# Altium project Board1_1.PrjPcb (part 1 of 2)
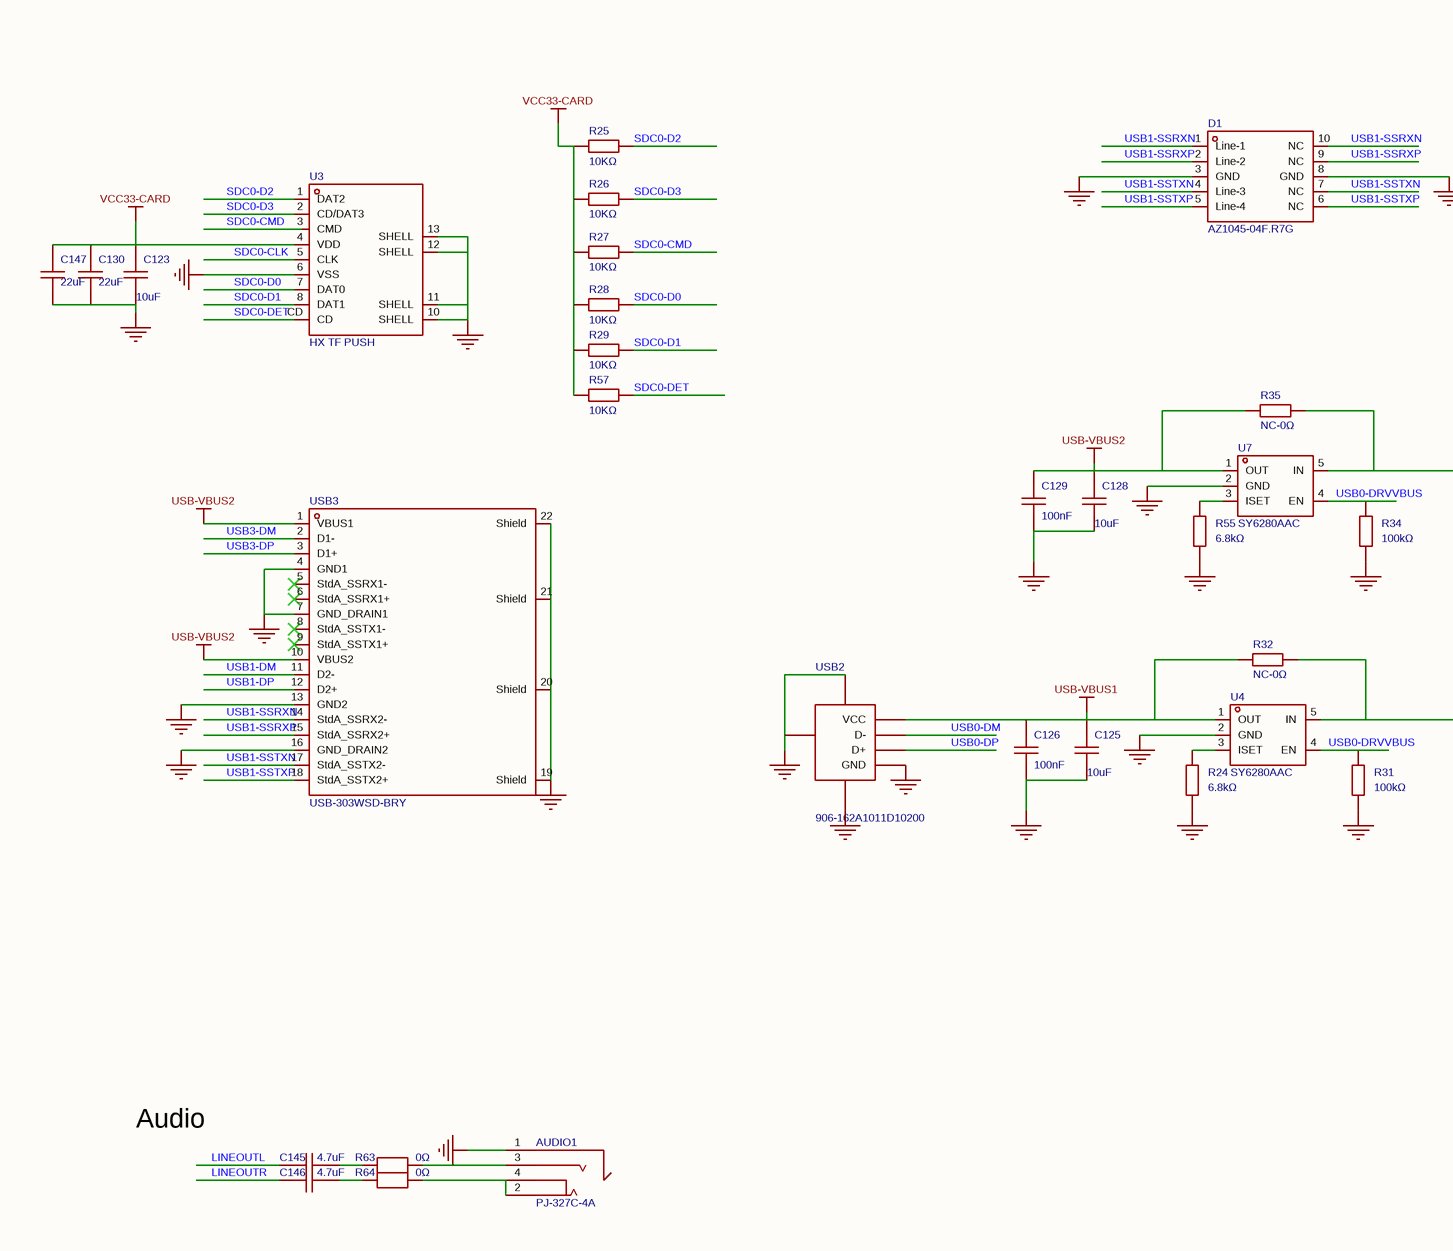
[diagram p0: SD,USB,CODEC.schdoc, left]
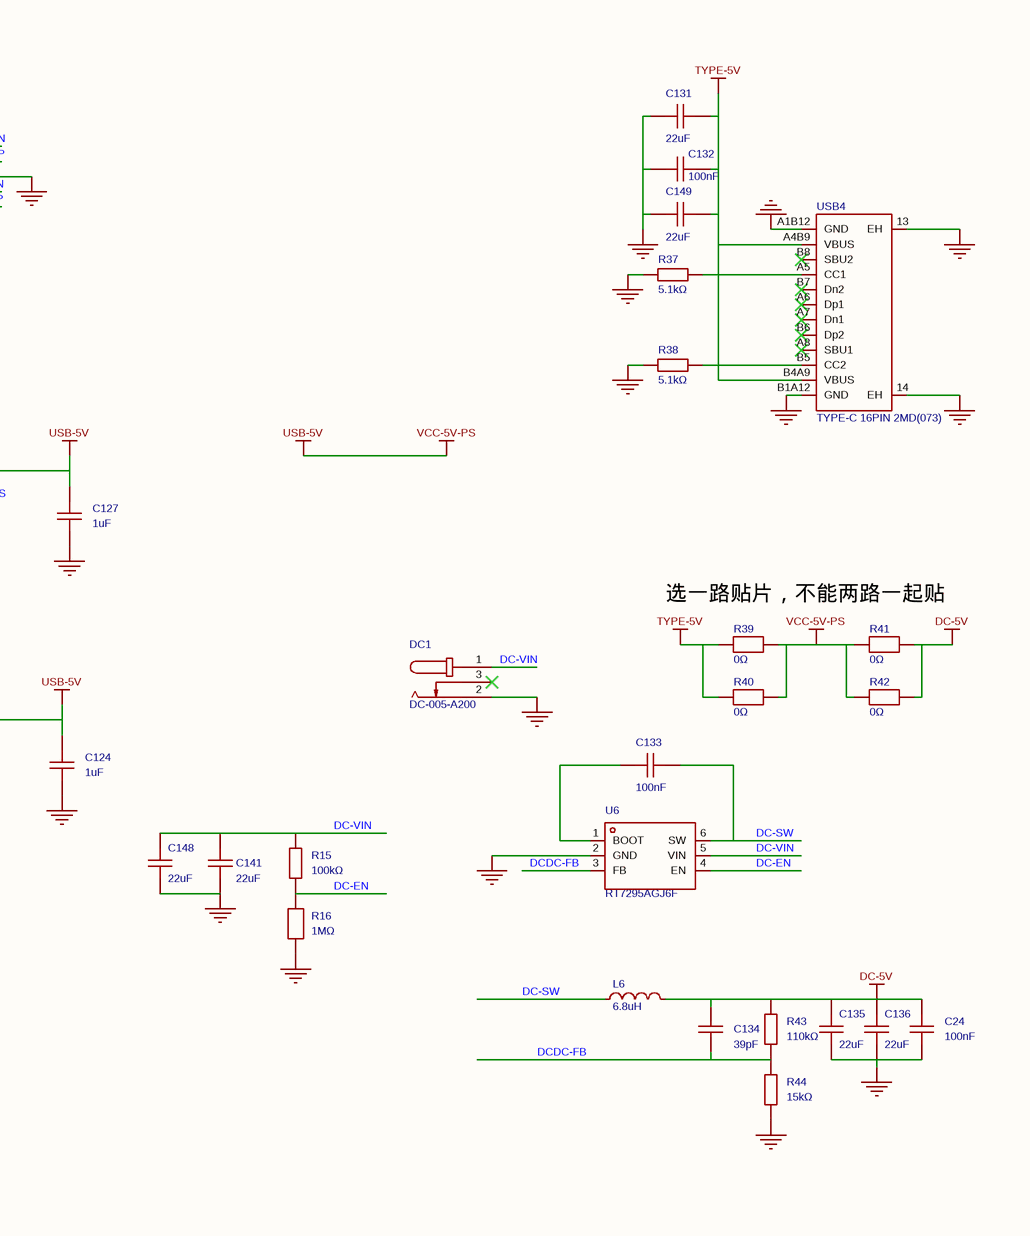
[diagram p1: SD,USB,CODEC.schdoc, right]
7 sheets, 256 parts. Net scope: global (net labels, ports and power ports of the same name join across sheets).
Board file: PCB1_1.pcbdoc
Sheets:
  SD,USB,CODEC.schdoc
  Lpddr3.schdoc
  H6_SOC_2.schdoc
  H6_SOC_1.schdoc
  Power_Tree_1.schdoc
  ETH,HDMI.schdoc
  KEY,DEBUG,LED.schdoc

## Sheet SD,USB,CODEC.schdoc
size 420 x 297 mm; Device: Drawing-Symbol_A4; @Board Name: Board1_1; @Page Name: SD,USB,CODEC; @Create Time: 13:52:28; @Page Count: 7; @Page No: 5; @Schematic Name: Schematic1_1; @Update Time: 13:52:28; @Assembly Variant: Basic; Border: 1; Title Block Position: 3; Size: A4; Region Start: 1; X Region Count: 6; Y Region Count: 4; Blade Width: 10; Width: 1655; Height: 1170; Symbol: Drawing-Symbol_A4; Company: 嘉立创EDA; Version: V1.0; Page Size: A4; @Project Name: N01｜全志 H6 Linux 主板; @Update Date: 2026-11-21; @Create Date: 2026-11-21

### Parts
AUDIO1  PJ-327C-4A  [AUDIO-SMD_PJ-327C-4A]
C24  100nF  [C0603]
C123  10uF  [C0603]
C124  1uF  [C0402]
C125  10uF  [C0603]
C126  100nF  [C0402]
C127  1uF  [C0402]
C128  10uF  [C0603]
C129  100nF  [C0402]
C130  22uF  [C0603]
C131  22uF  [C0603]
C132  100nF  [C0603]
C133  100nF  [C0603]
C134  39pF  [C0603]
C135  22uF  [C0603]
C136  22uF  [C0603]
C141  22uF  [C0603]
C145  4.7uF  [C0402]
C146  4.7uF  [C0402]
C147  22uF  [C0603]
C148  22uF  [C0603]
C149  22uF  [C0603]
D1  AZ1045-04F.R7G  [DFN2510-10_L2.5-W1.0-P0.50-BL]
DC1  DC-005-A200  [DC-IN-TH_DC-005-A200]
L6  6.8uH  [IND-SMD_L7.0-W6.6]
R15  100kΩ  [R0805]
R16  1MΩ  [R0805]
R24  6.8kΩ  [R0805]
R25  10KΩ  [R0805]
R26  10KΩ  [R0805]
R27  10KΩ  [R0805]
R28  10KΩ  [R0805]
R29  10KΩ  [R0805]
R31  100kΩ  [R0805]
R32  NC-0Ω  [R0805]
R34  100kΩ  [R0805]
R35  NC-0Ω  [R0805]
R37  5.1kΩ  [R0805]
R38  5.1kΩ  [R0805]
R39  0Ω  [R0805]
R40  0Ω  [R0805]
R41  0Ω  [R0805]
R42  0Ω  [R0805]
R43  110kΩ  [R0805]
R44  15kΩ  [R0805]
R55  6.8kΩ  [R0805]
R57  10KΩ  [R0805]
R63  0Ω  [R0805]
R64  0Ω  [R0805]
U3  HX TF PUSH  [TF-SMD_TF-PUSH]
U4  SY6280AAC  [SOT-23-5_L3.0-W1.7-P0.95-LS2.8-BL]
U6  RT7295AGJ6F  [SOT-23-6_L2.9-W1.6-P0.95-LS2.8-BR]
U7  SY6280AAC  [SOT-23-5_L3.0-W1.7-P0.95-LS2.8-BL]
USB2  906-162A1011D10200  [USB-A-TH_4P-P1.40-V-F-C39416]
USB3  USB-303WSD-BRY  [USB-A-TH_XUNPU_USB-303WSD-BRY]
USB4  TYPE-C 16PIN 2MD(073)  [USB-C-SMD_TYPE-C-16PIN-2MD-073]

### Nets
DC-5V: C24.2 C134.1 C135.2 C136.2 L6.2 R41.2 R42.2 R43.2
GND: AUDIO1.1 C24.1 C123.2 C124.1 C125.2 C126.1 C127.1 C128.2 C129.1 C130.1 C131.1 C132.2 C135.1 C136.1 C141.1 C147.1 C148.1 C149.2 D1.3(GND) D1.8(GND) DC1.2 R16.1 R24.1 R31.1 R34.1 R37.1 R38.1 R44.1 R55.1 U3.6(VSS) U3.10(SHELL) U3.11(SHELL) U3.12(SHELL) U3.13(SHELL) U4.2(GND) U6.2(GND) U7.2(GND) USB2.4(GND) USB2.5 USB2.6 USB2.7 USB3.4(GND1) USB3.7(GND_DRAIN1) USB3.13(GND2) USB3.16(GND_DRAIN2) USB3.19(Shield) USB3.20(Shield) USB3.21(Shield) USB3.22(Shield) USB4.13(EH) USB4.14(EH) USB4.A1B12(GND) USB4.B1A12(GND)
TYPE-5V: C131.2 C132.1 C149.1 R39.1 R40.1 USB4.A4B9(VBUS) USB4.B4A9(VBUS)
USB-5V: C124.2 C127.2 R32.1 R35.1 R39.2 R40.2 R41.1 R42.1 U4.5(IN) U7.5(IN)  [also labelled VCC-5V-PS]  [project net ALDOIN]
USB-VBUS1: C125.1 C126.2 R32.2 U4.1(OUT) USB2.1(VCC)
USB-VBUS2: C128.1 C129.2 R35.2 U7.1(OUT) USB3.1(VBUS1) USB3.10(VBUS2)
VCC33-CARD: C123.1 C130.2 C147.2 R25.2 R26.2 R27.2 R28.2 R29.2 R57.2 U3.4(VDD)  [project net CLDO1]
DC-EN: R15.1 R16.2 U6.4(EN)
DC-SW: C133.2 L6.1 U6.6(SW)
DC-VIN: C141.2 C148.2 DC1.1 R15.2 U6.5(VIN)
DCDC-FB: C134.2 R43.1 R44.2 U6.3(FB)
LINEOUTL: C145.2
LINEOUTR: C146.2
SDC0-CLK: U3.5(CLK)
SDC0-CMD: R27.1 U3.3(CMD)
SDC0-D0: R28.1 U3.7(DAT0)
SDC0-D1: R29.1 U3.8(DAT1)
SDC0-D2: R25.1 U3.1(DAT2)
SDC0-D3: R26.1 U3.2(CD/DAT3)
SDC0-DET: R57.1 U3.CD
USB0-DM: USB2.2(D-)
USB0-DP: USB2.3(D+)
USB0-DRVVBUS: R31.2 R34.2 U4.4(EN) U7.4(EN)
USB1-DM: USB3.11(D2-)
USB1-DP: USB3.12(D2+)
USB1-SSRXN: D1.1(Line-1) D1.10(NC) USB3.14(StdA_SSRX2-)
USB1-SSRXP: D1.2(Line-2) D1.9(NC) USB3.15(StdA_SSRX2+)
USB1-SSTXN: D1.4(Line-3) D1.7(NC) USB3.17(StdA_SSTX2-)
USB1-SSTXP: D1.5(Line-4) D1.6(NC) USB3.18(StdA_SSTX2+)
USB3-DM: USB3.2(D1-)
USB3-DP: USB3.3(D1+)
NetAUDIO1_2: AUDIO1.2 AUDIO1.4 R64.2
NetAUDIO1_3: AUDIO1.3 R63.2
NetC133_1: C133.1 U6.1(BOOT)
NetC145_1: C145.1 R63.1
NetC146_1: C146.1 R64.1
NetR24_2: R24.2 U4.3(ISET)
NetR37_2: R37.2 USB4.A5(CC1)
NetR38_2: R38.2 USB4.B5(CC2)
NetR55_2: R55.2 U7.3(ISET)

Not connected (* = marked no-connect by the designer): DC1 3*; USB3 5(StdA_SSRX1-)* 6(StdA_SSRX1+)* 8(StdA_SSTX1-)* 9(StdA_SSTX1+)*; USB4 A6(Dp1)* A7(Dn1)* A8(SBU1)* B6(Dp2)* B7(Dn2)* B8(SBU2)*

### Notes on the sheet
- (near R39) 选一路贴片，不能两路一起贴
- Audio

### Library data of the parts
AUDIO1 = PJ-327C-4A: 连接器类型:3.5mm耳机座;额定电流:500mA;额定电压:30V;触头材质:磷青铜;触头镀层:银;; Manufacturer: 韩国韩荣; AddInBom: yes; ModelId: b4a2275f591840bfadcc7ed8cf342a6c¦0819f05c4eef4c71ace90d822a990e87; ModelName: AUDIO-SMD_L11.8-W6.0-H5.0-4P; ModelTransform: 562.991,334.645,0,270,0,0,-7.124,73.506,-19.685; Current Rating: 500mA; Voltage Rating (Max): 30V
C24 C133 = FCC0603B104K500CT: 容值:100nF;精度:±10%;额定电压:50V;温度系数:X7R;; Manufacturer: FOJAN(富捷); 3D Model: ac125912035d415993ca9572d50418b1¦0819f05c4eef4c71ace90d822a990e87; 3D Model Transform: 62.992,31.496,0,0,0,0,0,0,0; Tolerance: ±10%; Voltage Rating: 50V; Temperature Coefficient: X7R; AddInBom: yes; ModelName: C0603_L1.6-W0.8-H0.8
C123 C125 C128 = CL10A106KP8NNNC: 容值:10uF;精度:±10%;额定电压:10V;温度系数:X5R;; Manufacturer: SAMSUNG(三星); 3D Model: ac125912035d415993ca9572d50418b1¦0819f05c4eef4c71ace90d822a990e87; 3D Model Transform: 62.992,31.496,0,0,0,0,0,0,0; Tolerance: ±10%; Voltage Rating: 10V; Temperature Coefficient: X5R; AddInBom: yes; ModelName: C0603_L1.6-W0.8-H0.8
C124 C127 = HGC0402R5105K500NTEJ: 容值:1uF;精度:±10%;额定电压:50V;温度系数:X5R;; Manufacturer: Chinocera(华瓷); 3D Model: 36a51122f27c49738f86b3bfa98863e0¦0819f05c4eef4c71ace90d822a990e87; 3D Model Transform: 39.37,19.685,0,0,0,0,0,0,0; Tolerance: ±10%; Voltage Rating: 50V; Temperature Coefficient: X5R; AddInBom: yes; ModelName: C0402_L1.0-W0.5-H0.5
C126 C129 = CL05B104KO5NNNC: 容值:100nF;精度:±10%;额定电压:16V;温度系数:X7R;; Manufacturer: SAMSUNG(三星); 3D Model: 36a51122f27c49738f86b3bfa98863e0¦0819f05c4eef4c71ace90d822a990e87; 3D Model Transform: 39.37,19.685,0,0,0,0,0,0,0; Tolerance: ±10%; Voltage Rating: 16V; Temperature Coefficient: X7R; AddInBom: yes; ModelName: C0402_L1.0-W0.5-H0.5
C130 C135 C136 C141 C147-C149 = HGC0603R5226M100NTHJ: 容值:22uF;精度:±20%;额定电压:10V;温度系数:X5R;; Manufacturer: Chinocera(华瓷); 3D Model: ac125912035d415993ca9572d50418b1¦0819f05c4eef4c71ace90d822a990e87; 3D Model Transform: 62.992,31.496,0,0,0,0,0,0,0; Tolerance: ±20%; Voltage Rating: 10V; Temperature Coefficient: X5R; AddInBom: yes; ModelName: C0603_L1.6-W0.8-H0.8
C131 = CGA0603X5R226M160JT: 容值:22uF;精度:±20%;额定电压:16V;温度系数:X5R;; Manufacturer: HRE(芯声); 3D Model: ac125912035d415993ca9572d50418b1¦0819f05c4eef4c71ace90d822a990e87; 3D Model Transform: 62.992,31.496,0,0,0,0,0,0,0; Tolerance: ±20%; Voltage Rating: 16V; Temperature Coefficient: X5R; AddInBom: yes; ModelName: C0603_L1.6-W0.8-H0.8
C132 = CGA0603X7R104K500JT: 容值:100nF;精度:±10%;额定电压:50V;温度系数:X7R;; Manufacturer: HRE(芯声); 3D Model: ac125912035d415993ca9572d50418b1¦0819f05c4eef4c71ace90d822a990e87; 3D Model Transform: 62.992,31.496,0,0,0,0,0,0,0; Tolerance: ±10%; Voltage Rating: 50V; Temperature Coefficient: X7R; AddInBom: yes; ModelName: C0603_L1.6-W0.8-H0.8
C134 = CC0603JRNPO9BN390: 容值:39pF;精度:±5%;额定电压:50V;温度系数:NP0;; Manufacturer: YAGEO(国巨); AddInBom: yes; ModelId: ac125912035d415993ca9572d50418b1¦0819f05c4eef4c71ace90d822a990e87; ModelName: C0603_L1.6-W0.8-H0.8; ModelTransform: 62.992,31.496,0,0,0,0,0,0,0; Tolerance: ±5%; Voltage Rating: 50V; Temperature Coefficient: NP0
C145 C146 = CL05A475KP5NRNC: 容值:4.7uF;精度:±10%;额定电压:10V;温度系数:X5R;; Manufacturer: SAMSUNG(三星); AddInBom: yes; ModelId: 36a51122f27c49738f86b3bfa98863e0¦0819f05c4eef4c71ace90d822a990e87; ModelName: C0402_L1.0-W0.5-H0.5; ModelTransform: 39.37,19.685,0,0,0,0,0,0,0; Tolerance: ±10%; Voltage Rating: 10V; Temperature Coefficient: X5R
D1 = AZ1045-04F.R7G: 反向截止电压(Vrwm):5V;钳位电压:12V;峰值脉冲电流(Ipp):3.5A@8/20us;峰值脉冲功率(Ppp):30W@8/20us;击穿电压:6V;; Manufacturer: AMAZING(晶焱); AddInBom: yes; ModelId: 55525fa8fc914f7c8ffcb10749ea5f73¦0819f05c4eef4c71ace90d822a990e87; ModelName: DFN-10_L2.5-W1.0-H0.5-P0.50; ModelTransform: 40.1574,98.425,0,90,0,0,0,0,0; Reverse Stand-Off Voltage (Vrwm): 5V; Clamping Voltage: 12V; Voltage - Breakdown: 6V; Reverse Leakage Current (Ir): 1.5uA; Number of Channels: 四路; level of protection: IEC 61000-4-5；IEC 61000-4-2; Type: ESD; Junction Capacitance: 0.5pF
DC1 = DC-005-A200: 连接器类型:DC电源插座;安装方式:弯插;触点内径:2mm;触点外径:6.4mm;额定电流:3A;额定电压:30V;工作温度:-20℃~+70℃;; Manufacturer: XUNPU(讯普); AddInBom: yes; ModelId: 1321cdbe1dc84555a9684967491c8670¦0819f05c4eef4c71ace90d822a990e87; ModelTransform: 553.149,368.14887,0,0,0,0,-137.795,85.63,-161.417; Connector Type: DC电源插座; Inside Contact Diameter: 2mm; Outside Contact Diameter: 6.4mm; Current Rating: 3A; Voltage Rating (Max): 30V
L6 = FXL0630-6R8-M: 电感值:6.8uH;精度:±20%;额定电流:5A;饱和电流(Isat):6A;类型:一体成型电感;; Manufacturer: cjiang(长江微电); AddInBom: yes; ModelId: 6860c29aec394a38a0f014af7f722a42¦0819f05c4eef4c71ace90d822a990e87; ModelName: IND-SMD_L7.0-W6.6-H3.0; ModelTransform: 275.59,259.88137,0,0,0,0,0,0,0; Tolerance: ±20%; Current Rating: 5A; Current - Saturation(Isat): 6A; DC Resistance(DCR): 48mΩ; Type: 一体成型电感
R15 = 0805W8F1003T5E: 电阻类型:厚膜电阻;阻值:100kΩ;精度:±1%;功率:125mW;工作电压:150V;温度系数:±100ppm/℃;; Manufacturer: UNI-ROYAL(厚声); Symbol: 0805W8F1003T5E_C149504; 3D Model: 37a81e68749a4138bd2dfa6897b24b85¦0819f05c4eef4c71ace90d822a990e87; 3D Model Transform: 78.74,51.181,0,0,0,0,0,-0.0005,0; Tolerance: ±1%; Power(Watts): 125mW; Voltage-Supply(Max): 150V; AddInBom: yes; ModelName: R0805_L2.0-W1.3-H0.6
R16 = AS051MF: 阻值:1MΩ;精度:±1%;功率:125mW;工作电压:150V;温度系数:±100ppm/℃;; Manufacturer: HKR(香港电阻); AddInBom: yes; ModelId: 37a81e68749a4138bd2dfa6897b24b85¦0819f05c4eef4c71ace90d822a990e87; ModelName: R0805_L2.0-W1.3-H0.6; ModelTransform: 78.74,51.181,0,0,0,0,0,-0.0005,0; Tolerance: ±1%; Power(Watts): 125mW; Voltage-Supply(Max): 150V
R24 R55 = 0805W8F6801T5E: 电阻类型:厚膜电阻;阻值:6.8kΩ;精度:±1%;功率:125mW;工作电压:150V;温度系数:±100ppm/℃;; Manufacturer: UNI-ROYAL(厚声); AddInBom: yes; ModelId: 37a81e68749a4138bd2dfa6897b24b85¦0819f05c4eef4c71ace90d822a990e87; ModelName: R0805_L2.0-W1.3-H0.6; ModelTransform: 78.74,51.181,0,0,0,0,0,-0.0005,0; Tolerance: ±1%; Power(Watts): 125mW; Voltage-Supply(Max): 150V
R25-R29 R57 = 0805W8F1002T5E_C17414: 电阻类型:厚膜电阻;阻值:10kΩ;精度:±1%;功率:125mW;工作电压:150V;温度系数:±100ppm/℃;; Manufacturer: UNI-ROYAL(厚声); Add into BOM: yes; 3D Model: 37a81e68749a4138bd2dfa6897b24b85; 3D Model Transform: 78.74,51.181,0,0,0,0,0,-0.0005,0; Tolerance: ±1%; Power(Watts): 125mW; Voltage-Supply(Max): 150V; ModelName: R0805_L2.0-W1.3-H0.6
R31 R32 R34 R35 = 0805W8F1003T5E: 电阻类型:厚膜电阻;阻值:100kΩ;精度:±1%;功率:125mW;工作电压:150V;温度系数:±100ppm/℃;; Manufacturer: UNI-ROYAL(厚声); Symbol: 0805W8F1003T5E_C149504; AddInBom: yes; ModelId: 37a81e68749a4138bd2dfa6897b24b85¦0819f05c4eef4c71ace90d822a990e87; ModelName: R0805_L2.0-W1.3-H0.6; ModelTransform: 78.74,51.181,0,0,0,0,0,-0.0005,0; Tolerance: ±1%; Power(Watts): 125mW; Voltage-Supply(Max): 150V
R37 R38 = 0805W8F5101T5E: 电阻类型:厚膜电阻;阻值:5.1kΩ;精度:±1%;功率:125mW;工作电压:150V;温度系数:±100ppm/℃;; Manufacturer: UNI-ROYAL(厚声); 3D Model: 37a81e68749a4138bd2dfa6897b24b85¦0819f05c4eef4c71ace90d822a990e87; 3D Model Transform: 78.74,51.181,0,0,0,0,0,-0.0005,0; Tolerance: ±1%; Power(Watts): 125mW; Voltage-Supply(Max): 150V; AddInBom: yes; ModelName: R0805_L2.0-W1.3-H0.6
R39-R42 R63 R64 = RE0805FAR000: 电阻类型:合金电阻;阻值:0Ω;精度:±1%;功率:500mW;温度系数:±50ppm/℃;安装方式:贴片;; Manufacturer: JIERR(捷而瑞); 3D Model: 37a81e68749a4138bd2dfa6897b24b85¦0819f05c4eef4c71ace90d822a990e87; 3D Model Transform: 78.74,51.181,0,0,0,0,0,-0.0005,0; Tolerance: ±1%; Power(Watts): 500mW; AddInBom: yes; ModelName: R0805_L2.0-W1.3-H0.6
R43 = 0805W8F1103T5E: 电阻类型:厚膜电阻;阻值:110kΩ;精度:±1%;功率:125mW;工作电压:150V;温度系数:±100ppm/℃;; Manufacturer: UNI-ROYAL(厚声); AddInBom: yes; ModelId: 37a81e68749a4138bd2dfa6897b24b85¦0819f05c4eef4c71ace90d822a990e87; ModelName: R0805_L2.0-W1.3-H0.6; ModelTransform: 78.74,51.181,0,0,0,0,0,-0.0005,0; Tolerance: ±1%; Power(Watts): 125mW; Voltage-Supply(Max): 150V
R44 = 0805W8F1502T5E: 电阻类型:厚膜电阻;阻值:15kΩ;精度:±1%;功率:125mW;工作电压:150V;温度系数:±100ppm/℃;; Manufacturer: UNI-ROYAL(厚声); AddInBom: yes; ModelId: 37a81e68749a4138bd2dfa6897b24b85¦0819f05c4eef4c71ace90d822a990e87; ModelName: R0805_L2.0-W1.3-H0.6; ModelTransform: 78.74,51.181,0,0,0,0,0,-0.0005,0; Tolerance: ±1%; Power(Watts): 125mW; Voltage-Supply(Max): 150V
U3 = HX TF PUSH: 卡连接方式:自弹式;卡类型:MicroSD卡(TF卡);连接器类型:卡座;本体最大高度:2mm;工作温度:-20℃~+70℃;; Manufacturer: hanxia(韩下); 3D Model: 2d6270e77c9a43c6bb0aca962ba811a2¦0819f05c4eef4c71ace90d822a990e87; 3D Model Transform: 635.826,598.424,0,0,0,0,0.002,-82.441,-23.622; Card Connection Mode: 自弹式; Connector Type: 卡座; Additional Card Detection Pins: 有; Rated Voltage (Max): 5V; AddInBom: yes
U4 U7 = SY6280AAC_C55136: 类型:高侧开关;通道数:1;输入控制逻辑:高电平有效;工作电压:2.4V~5.5V;最大连续电流:2A;导通电阻:80mΩ;; Manufacturer: Silergy(矽力杰); AddInBom: yes; ModelId: 0a2a1b8f50944f73965918ad6e5fe167¦0819f05c4eef4c71ace90d822a990e87; ModelName: SOT-23-5_L2.9-W1.6-H1.1-LS2.8-P0.95; ModelTransform: 118.60433,114.173,0,90,0,0,0.0005,0.0005,0; Number of Channels: 1; Control Input Logic: 高电平有效; Maximum Continuous Current: 2A; RDS(on): 80mΩ
U6 = RT7295AGJ6F: 功能类型:降压型;工作电压:4.3V~18V;输出电压:600mV~8V;输出电流:3.5A;输出类型:可调;; Manufacturer: RICHTEK(立锜); AddInBom: yes; ModelId: 18da8f6c14a34920b3e136b5c401a119¦0819f05c4eef4c71ace90d822a990e87; ModelName: SOT-23-6_L2.9-W1.6-H1.5-LS2.8-P0.95; ModelTransform: 110.73671,114.173,0,180,0,0,0.001,-0.003,0; Function: 降压型; Output Current: 3.5A; Frequency - Switching: 500kHz; Synchronous Rectifier: 是; Number of Outputs: 1; Topology: 降压式; Quiescent Current: 500uA; Switch tube (built-in/external): 内置; Output Type: 可调
USB2 = 906-162A1011D10200: 连接器类型:Type-A;协议标准:USB 2.0;公母:母;安装方式:侧插;触点数量:4P;端口数量:1;额定电流 - 电源:2A;工作温度:-;; Manufacturer: 精拓金; Symbol: AFSide of the three straight feet boundless copper14.0PBTWhite plastic90degree; AddInBom: yes; ModelId: bcfe7919af774627a59aba49c9f8feb0¦0819f05c4eef4c71ace90d822a990e87; ModelTransform: 280.3144,555.121,0,0,0,0,0,-74.212,-118.11; Connector Type: Type-A; Protocol Standard: USB 2.0; Gender: 母; Number of Contacts: 4P; Number of Ports: 1; Current Rating-Power: 2A; Voltage Rating: 30V; Connect-Disconnect Life: 1.5千次
USB3 = USB-303WSD-BRY: 连接器类型:Type-A;协议标准:USB 3.0;公母:母;安装方式:弯插;触点数量:9Px2;端口数量:2;额定电流 - 电源:1.8A;工作温度:-30℃~+85℃;; Manufacturer: XUNPU(讯普); AddInBom: yes; ModelId: 099f7116bbdc404e98854c37ac96170a¦0819f05c4eef4c71ace90d822a990e87; ModelTransform: 614.147,688.975,0,0,0,0,0,-166.339,-118.11; Connector Type: Type-A; Protocol Standard: USB 3.0; Gender: 母; Number of Contacts: 9Px2; Number of Ports: 2; Current Rating-Power: 1.8A; Voltage Rating: 30V; Detection color: 蓝色
USB4 = TYPE-C 16PIN 2MD(073): 连接器类型:Type-C;协议标准:-;公母:母;安装方式:卧贴;触点数量:16P;端口数量:1;额定电流 - 电源:3A;工作温度:-25℃~+85℃;; Manufacturer: SHOU HAN(首韩); Add into BOM: yes; 3D Model: 3a41b9ec9b654a0fad4d118405ec6290; 3D Model Transform: 351.9678,298.4246,0,0,0,0,0,-47.244,-35.433; Gender: 母; Number of Contacts: 16P; Number of Ports: 1; Current Rating-Power: 3A; Voltage Rating: 5V; Connect-Disconnect Life: 1万次; Detection color: 黑色; ModelName: USB-C-SMD_TYPE-C-6PIN-2MD-073

## Sheet Lpddr3.schdoc
size 420 x 297 mm; Device: Drawing-Symbol_A4; @Board Name: Board1_1; @Page Name: Lpddr3; @Create Time: 13:52:28; @Page Count: 7; @Page No: 4; @Schematic Name: Schematic1_1; @Update Time: 13:52:28; @Assembly Variant: Basic; Border: 1; Title Block Position: 3; Size: A4; Region Start: 1; X Region Count: 6; Y Region Count: 4; Blade Width: 10; Width: 1655; Height: 1170; Symbol: Drawing-Symbol_A4; Company: 嘉立创EDA; Version: V1.0; Page Size: A4; @Project Name: N01｜全志 H6 Linux 主板; @Update Date: 2026-11-21; @Create Date: 2026-11-21
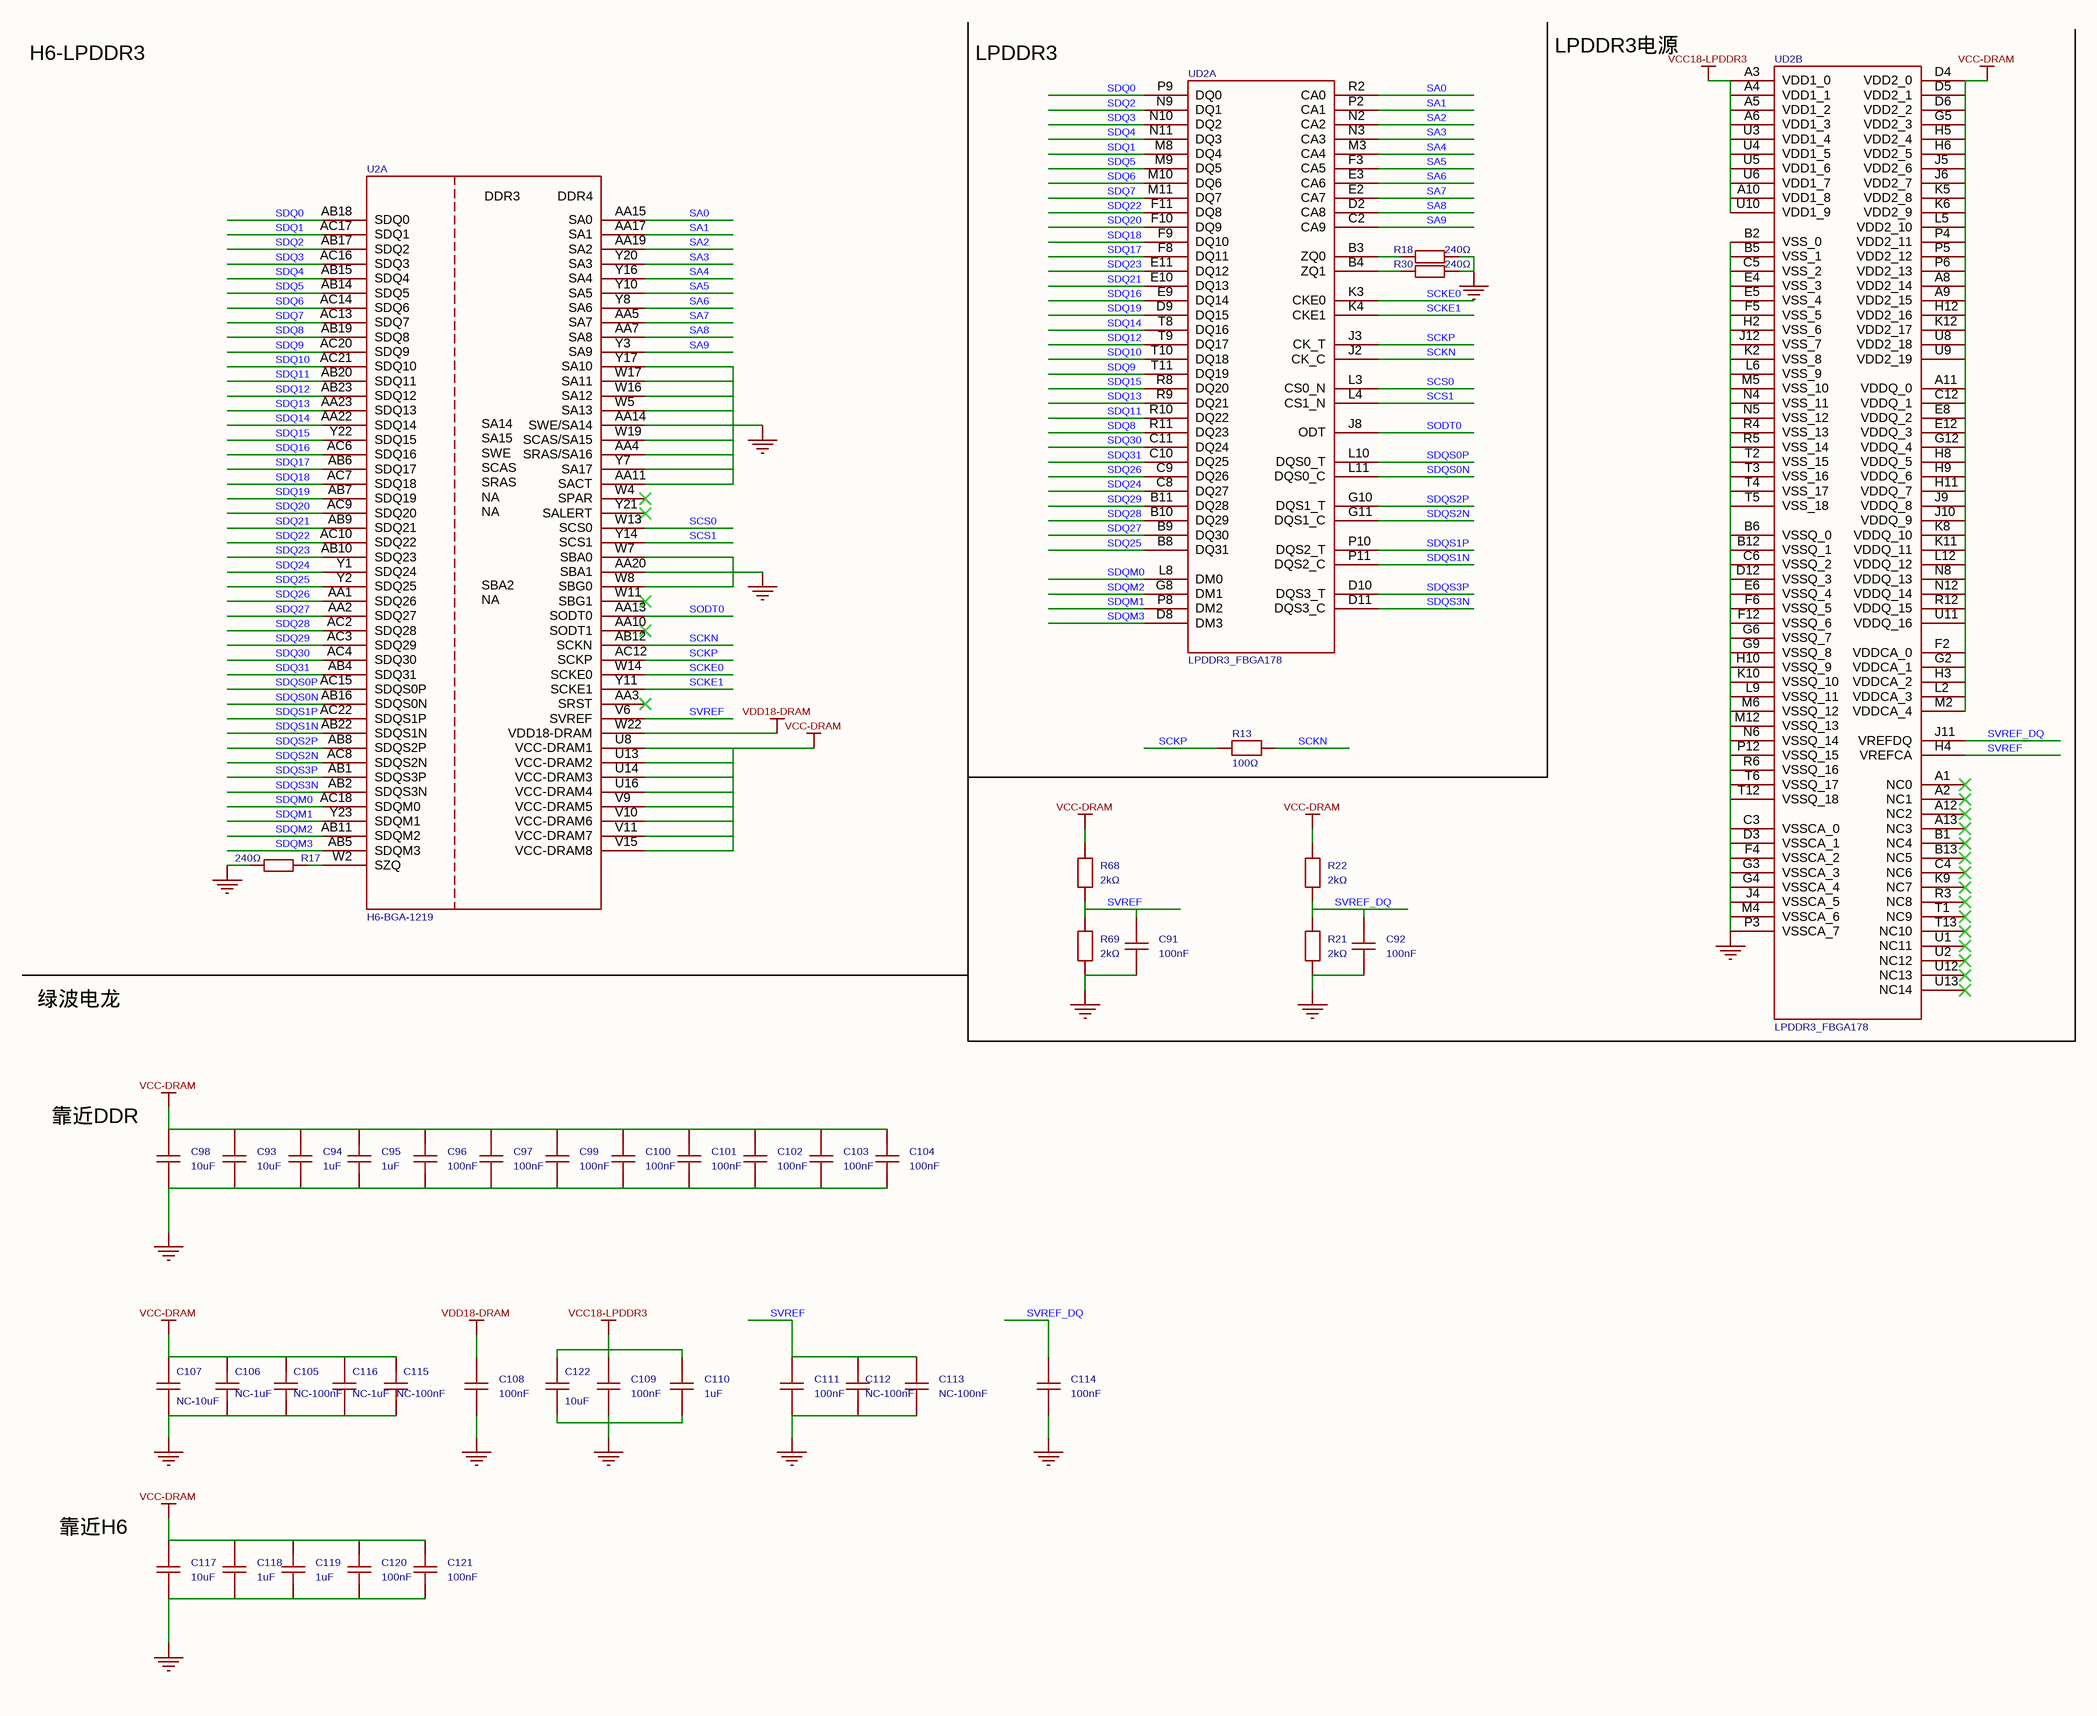
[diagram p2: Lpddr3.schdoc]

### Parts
C91  100nF  [C0402]
C92  100nF  [C0402]
C93  10uF  [C0603]
C94  1uF  [C0402]
C95  1uF  [C0402]
C96  100nF  [C0402]
C97  100nF  [C0402]
C98  10uF  [C0603]
C99  100nF  [C0402]
C100  100nF  [C0402]
C101  100nF  [C0402]
C102  100nF  [C0402]
C103  100nF  [C0402]
C104  100nF  [C0402]
C105  NC-100nF  [C0402]
C106  NC-1uF  [C0402]
C107  NC-10uF  [C0603]
C108  100nF  [C0402]
C109  100nF  [C0402]
C110  1uF  [C0402]
C111  100nF  [C0402]
C112  NC-100nF  [C0402]
C113  NC-100nF  [C0402]
C114  100nF  [C0402]
C115  NC-100nF  [C0402]
C116  NC-1uF  [C0402]
C117  10uF  [C0603]
C118  1uF  [C0402]
C119  1uF  [C0402]
C120  100nF  [C0402]
C121  100nF  [C0402]
C122  10uF  [C0603]
R13  100Ω  [R0805]
R17  240Ω  [R0805]
R18  240Ω  [R0805]
R21  2kΩ  [R0402]
R22  2kΩ  [R0402]
R30  240Ω  [R0805]
R68  2kΩ  [R0402]
R69  2kΩ  [R0402]
U2  H6-BGA-1219  [H6_BGA451]  (part A of 4)
UD2  LPDDR3_FBGA178  [LPDDR3_FBGA178]  (parts A,B of 2)

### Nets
GND: C91.1 C92.1 C93.1 C94.1 C95.1 C96.1 C97.1 C98.1 C99.1 C100.1 C101.1 C102.1 C103.1 C104.1 C105.1 C106.1 C107.1 C108.1 C109.1 C110.1 C111.1 C112.1 C113.1 C114.1 C115.1 C116.1 C117.1 C118.1 C119.1 C120.1 C121.1 C122.1 R17.1 R18.2 R21.1 R30.2 R69.1 U2.AA4(SRAS/SA16) U2.AA11(SACT) U2.AA14(SWE/SA14) U2.AA20(SBA1) U2.W5(SA13) U2.W7(SBA0) U2.W8(SBG0) U2.W16(SA12) U2.W17(SA11) U2.W19(SCAS/SA15) U2.Y7(SA17) U2.Y17(SA10) UD2.B2(VSS_0) UD2.B5(VSS_1) UD2.B6(VSSQ_0) UD2.B12(VSSQ_1) UD2.C3(VSSCA_0) UD2.C5(VSS_2) UD2.C6(VSSQ_2) UD2.D3(VSSCA_1) UD2.D12(VSSQ_3) UD2.E4(VSS_3) UD2.E5(VSS_4) UD2.E6(VSSQ_4) UD2.F4(VSSCA_2) UD2.F5(VSS_5) UD2.F6(VSSQ_5) UD2.F12(VSSQ_6) UD2.G3(VSSCA_3) UD2.G4(VSSCA_4) UD2.G6(VSSQ_7) UD2.G9(VSSQ_8) UD2.H2(VSS_6) UD2.H10(VSSQ_9) UD2.J4(VSSCA_5) UD2.J12(VSS_7) UD2.K2(VSS_8) UD2.K10(VSSQ_10) UD2.L6(VSS_9) UD2.L9(VSSQ_11) UD2.M4(VSSCA_6) UD2.M5(VSS_10) UD2.M6(VSSQ_12) UD2.M12(VSSQ_13) UD2.N4(VSS_11) UD2.N5(VSS_12) UD2.N6(VSSQ_14) UD2.P3(VSSCA_7) UD2.P12(VSSQ_15) UD2.R4(VSS_13) UD2.R5(VSS_14) UD2.R6(VSSQ_16) UD2.T2(VSS_15) UD2.T3(VSS_16) UD2.T4(VSS_17) UD2.T5(VSS_18) UD2.T6(VSSQ_17) UD2.T12(VSSQ_18)
VCC18-LPDDR3: C109.2 C110.2 C122.2 UD2.A3(VDD1_0) UD2.A4(VDD1_1) UD2.A5(VDD1_2) UD2.A6(VDD1_3) UD2.A10(VDD1_8) UD2.U3(VDD1_4) UD2.U4(VDD1_5) UD2.U5(VDD1_6) UD2.U6(VDD1_7) UD2.U10(VDD1_9)
VCC-DRAM: C93.2 C94.2 C95.2 C96.2 C97.2 C98.2 C99.2 C100.2 C101.2 C102.2 C103.2 C104.2 C105.2 C106.2 C107.2 C115.2 C116.2 C117.2 C118.2 C119.2 C120.2 C121.2 R22.2 R68.2 U2.U8(VCC-DRAM1) U2.U13(VCC-DRAM2) U2.U14(VCC-DRAM3) U2.U16(VCC-DRAM4) U2.V9(VCC-DRAM5) U2.V10(VCC-DRAM6) U2.V11(VCC-DRAM7) U2.V15(VCC-DRAM8) UD2.A8(VDD2_14) UD2.A9(VDD2_15) UD2.A11(VDDQ_0) UD2.C12(VDDQ_1) UD2.D4(VDD2_0) UD2.D5(VDD2_1) UD2.D6(VDD2_2) UD2.E8(VDDQ_2) UD2.E12(VDDQ_3) UD2.F2(VDDCA_0) UD2.G2(VDDCA_1) UD2.G5(VDD2_3) UD2.G12(VDDQ_4) UD2.H3(VDDCA_2) UD2.H5(VDD2_4) UD2.H6(VDD2_5) UD2.H8(VDDQ_5) UD2.H9(VDDQ_6) UD2.H11(VDDQ_7) UD2.H12(VDD2_16) UD2.J5(VDD2_6) UD2.J6(VDD2_7) UD2.J9(VDDQ_8) UD2.J10(VDDQ_9) UD2.K5(VDD2_8) UD2.K6(VDD2_9) UD2.K8(VDDQ_10) UD2.K11(VDDQ_11) UD2.K12(VDD2_17) UD2.L2(VDDCA_3) UD2.L5(VDD2_10) UD2.L12(VDDQ_12) UD2.M2(VDDCA_4) UD2.N8(VDDQ_13) UD2.N12(VDDQ_14) UD2.P4(VDD2_11) UD2.P5(VDD2_12) UD2.P6(VDD2_13) UD2.R12(VDDQ_15) UD2.U8(VDD2_18) UD2.U9(VDD2_19) UD2.U11(VDDQ_16)  [project net DCDCE]
VDD18-DRAM: C108.2 U2.W22(VDD18-DRAM)  [project net BLDO1]
SA0: U2.AA15(SA0) UD2.R2(CA0)
SA1: U2.AA17(SA1) UD2.P2(CA1)
SA2: U2.AA19(SA2) UD2.N2(CA2)
SA3: U2.Y20(SA3) UD2.N3(CA3)
SA4: U2.Y16(SA4) UD2.M3(CA4)
SA5: U2.Y10(SA5) UD2.F3(CA5)
SA6: U2.Y8(SA6) UD2.E3(CA6)
SA7: U2.AA5(SA7) UD2.E2(CA7)
SA8: U2.AA7(SA8) UD2.D2(CA8)
SA9: U2.Y3(SA9) UD2.C2(CA9)
SCKE0: U2.W14(SCKE0) UD2.K3(CKE0)
SCKE1: U2.Y11(SCKE1) UD2.K4(CKE1)
SCKN: R13.2 U2.AB12(SCKN) UD2.J2(CK_C)
SCKP: R13.1 U2.AC12(SCKP) UD2.J3(CK_T)
SCS0: U2.W13(SCS0) UD2.L3(CS0_N)
SCS1: U2.Y14(SCS1) UD2.L4(CS1_N)
SDQ0: U2.AB18(SDQ0) UD2.P9(DQ0)
SDQ1: U2.AC17(SDQ1) UD2.M8(DQ4)
SDQ2: U2.AB17(SDQ2) UD2.N9(DQ1)
SDQ3: U2.AC16(SDQ3) UD2.N10(DQ2)
SDQ4: U2.AB15(SDQ4) UD2.N11(DQ3)
SDQ5: U2.AB14(SDQ5) UD2.M9(DQ5)
SDQ6: U2.AC14(SDQ6) UD2.M10(DQ6)
SDQ7: U2.AC13(SDQ7) UD2.M11(DQ7)
SDQ8: U2.AB19(SDQ8) UD2.R11(DQ23)
SDQ9: U2.AC20(SDQ9) UD2.T11(DQ19)
SDQ10: U2.AC21(SDQ10) UD2.T10(DQ18)
SDQ11: U2.AB20(SDQ11) UD2.R10(DQ22)
SDQ12: U2.AB23(SDQ12) UD2.T9(DQ17)
SDQ13: U2.AA23(SDQ13) UD2.R9(DQ21)
SDQ14: U2.AA22(SDQ14) UD2.T8(DQ16)
SDQ15: U2.Y22(SDQ15) UD2.R8(DQ20)
SDQ16: U2.AC6(SDQ16) UD2.E9(DQ14)
SDQ17: U2.AB6(SDQ17) UD2.F8(DQ11)
SDQ18: U2.AC7(SDQ18) UD2.F9(DQ10)
SDQ19: U2.AB7(SDQ19) UD2.D9(DQ15)
SDQ20: U2.AC9(SDQ20) UD2.F10(DQ9)
SDQ21: U2.AB9(SDQ21) UD2.E10(DQ13)
SDQ22: U2.AC10(SDQ22) UD2.F11(DQ8)
SDQ23: U2.AB10(SDQ23) UD2.E11(DQ12)
SDQ24: U2.Y1(SDQ24) UD2.C8(DQ27)
SDQ25: U2.Y2(SDQ25) UD2.B8(DQ31)
SDQ26: U2.AA1(SDQ26) UD2.C9(DQ26)
SDQ27: U2.AA2(SDQ27) UD2.B9(DQ30)
SDQ28: U2.AC2(SDQ28) UD2.B10(DQ29)
SDQ29: U2.AC3(SDQ29) UD2.B11(DQ28)
SDQ30: U2.AC4(SDQ30) UD2.C11(DQ24)
SDQ31: U2.AB4(SDQ31) UD2.C10(DQ25)
SDQM0: U2.AC18(SDQM0) UD2.L8(DM0)
SDQM1: U2.Y23(SDQM1) UD2.P8(DM2)
SDQM2: U2.AB11(SDQM2) UD2.G8(DM1)
SDQM3: U2.AB5(SDQM3) UD2.D8(DM3)
SDQS0N: U2.AB16(SDQS0N) UD2.L11(DQS0_C)
SDQS0P: U2.AC15(SDQS0P) UD2.L10(DQS0_T)
SDQS1N: U2.AB22(SDQS1N) UD2.P11(DQS2_C)
SDQS1P: U2.AC22(SDQS1P) UD2.P10(DQS2_T)
SDQS2N: U2.AC8(SDQS2N) UD2.G11(DQS1_C)
SDQS2P: U2.AB8(SDQS2P) UD2.G10(DQS1_T)
SDQS3N: U2.AB2(SDQS3N) UD2.D11(DQS3_C)
SDQS3P: U2.AB1(SDQS3P) UD2.D10(DQS3_T)
SODT0: U2.AA13(SODT0) UD2.J8(ODT)
SVREF: C91.2 C111.2 C112.2 C113.2 R68.1 R69.2 U2.V6(SVREF) UD2.H4(VREFCA)
SVREF_DQ: C92.2 C114.2 R21.2 R22.1 UD2.J11(VREFDQ)
NetR17_2: R17.2 U2.W2(SZQ)
NetR18_1: R18.1 UD2.B3(ZQ0)
NetR30_1: R30.1 UD2.B4(ZQ1)

Not connected (* = marked no-connect by the designer): U2 AA3(SRST)* AA10(SODT1)* W4(SPAR)* W11(SBG1)* Y21(SALERT)*; UD2 A1(NC0)* A2(NC1)* A12(NC2)* A13(NC3)* B1(NC4)* B13(NC5)* C4(NC6)* K9(NC7)* R3(NC8)* T1(NC9)* T13(NC10)* U1(NC11)* U2(NC12)* U12(NC13)* U13(NC14)*

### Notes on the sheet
- H6-LPDDR3
- LPDDR3
- LPDDR3电源
- 绿波电龙
- 靠近DDR
- 靠近H6

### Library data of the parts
C91 C92 C96 C97 C99-C105 C108 C109 C111-C115 C120 C121 = CL05B104KO5NNNC: as C126 on sheet SD,USB,CODEC
C93 C98 C107 C117 C122 = FCC0603X106K100CT: 容值:10uF;精度:±10%;额定电压:10V;温度系数:X5R;; Manufacturer: FOJAN(富捷); 3D Model: ac125912035d415993ca9572d50418b1¦0819f05c4eef4c71ace90d822a990e87; 3D Model Transform: 62.992,31.496,0,0,0,0,0,0,0; Tolerance: ±10%; Voltage Rating: 10V; Temperature Coefficient: X5R; AddInBom: yes; ModelName: C0603_L1.6-W0.8-H0.8
C94 C95 C106 C110 C116 C118 C119 = HGC0402R5105K500NTEJ: as C124 on sheet SD,USB,CODEC
R13 = FRC0805F1000TS: 电阻类型:厚膜电阻;阻值:100Ω;精度:±1%;功率:125mW;工作电压:150V;温度系数:±100ppm/℃;; Manufacturer: FOJAN(富捷); AddInBom: yes; ModelId: 37a81e68749a4138bd2dfa6897b24b85¦0819f05c4eef4c71ace90d822a990e87; ModelName: R0805_L2.0-W1.3-H0.6; ModelTransform: 78.74,51.181,0,0,0,0,0,-0.0005,0; Tolerance: ±1%; Power(Watts): 125mW; Voltage-Supply(Max): 150V
R17 R18 = 0805W8F2400T5E: 电阻类型:厚膜电阻;阻值:240Ω;精度:±1%;功率:125mW;工作电压:150V;温度系数:±100ppm/℃;; Manufacturer: UNI-ROYAL(厚声); AddInBom: yes; ModelId: 37a81e68749a4138bd2dfa6897b24b85¦0819f05c4eef4c71ace90d822a990e87; ModelName: R0805_L2.0-W1.3-H0.6; ModelTransform: 78.74,51.181,0,0,0,0,0,-0.0005,0; Tolerance: ±1%; Power(Watts): 125mW; Voltage-Supply(Max): 150V
R21 R22 R68 R69 = FRC0402F2001TS: 电阻类型:厚膜电阻;阻值:2kΩ;精度:±1%;功率:62.5mW;工作电压:50V;温度系数:±100ppm/℃;; Manufacturer: FOJAN(富捷); AddInBom: yes; ModelId: 98c88bc2b9094f218f3a3e30a7012738¦0819f05c4eef4c71ace90d822a990e87; ModelName: R0402_L1.0-W0.5-H0.4; ModelTransform: 39.37,19.685,0,0,0,0,0,0,0; Tolerance: ±1%; Power(Watts): 62.5mW; Voltage-Supply(Max): 50V
R30 = 0805W8F2400T5E: 电阻类型:厚膜电阻;阻值:240Ω;精度:±1%;功率:125mW;工作电压:150V;温度系数:±100ppm/℃;; Manufacturer: UNI-ROYAL(厚声); 3D Model: 37a81e68749a4138bd2dfa6897b24b85¦0819f05c4eef4c71ace90d822a990e87; 3D Model Transform: 78.74,51.181,0,0,0,0,0,-0.0005,0; Tolerance: ±1%; Power(Watts): 125mW; Voltage-Supply(Max): 150V; AddInBom: yes; ModelName: R0805_L2.0-W1.3-H0.6
U2 = H6-BGA-1219: Value: 1; Relevance: []; SPLIT_INST: TRUE; SWAP_INFO: (S1+S2+S3+S4); componentDisplayMode: -1; AddInBom: yes; OriginFootprint: BGA451P65B1500_1500H118
UD2 = LPDDR3_FBGA178: Relevance: []; componentDisplayMode: -1; Value: 1; SPLIT_INST: TRUE; SWAP_INFO: (S1+S2); AddInBom: yes

## Sheet H6_SOC_2.schdoc
size 420 x 297 mm; Device: Drawing-Symbol_A4; @Board Name: Board1_1; @Page Name: H6_SOC_2; @Create Time: 13:52:28; @Page Count: 7; @Page No: 3; @Schematic Name: Schematic1_1; @Update Time: 13:52:28; @Assembly Variant: Basic; Border: 1; Title Block Position: 3; Size: A4; Region Start: 1; X Region Count: 6; Y Region Count: 4; Blade Width: 10; Width: 1655; Height: 1170; Symbol: Drawing-Symbol_A4; Company: 嘉立创EDA; Version: V1.0; Page Size: A4; @Project Name: N01｜全志 H6 Linux 主板; @Update Date: 2026-11-21; @Create Date: 2026-11-21
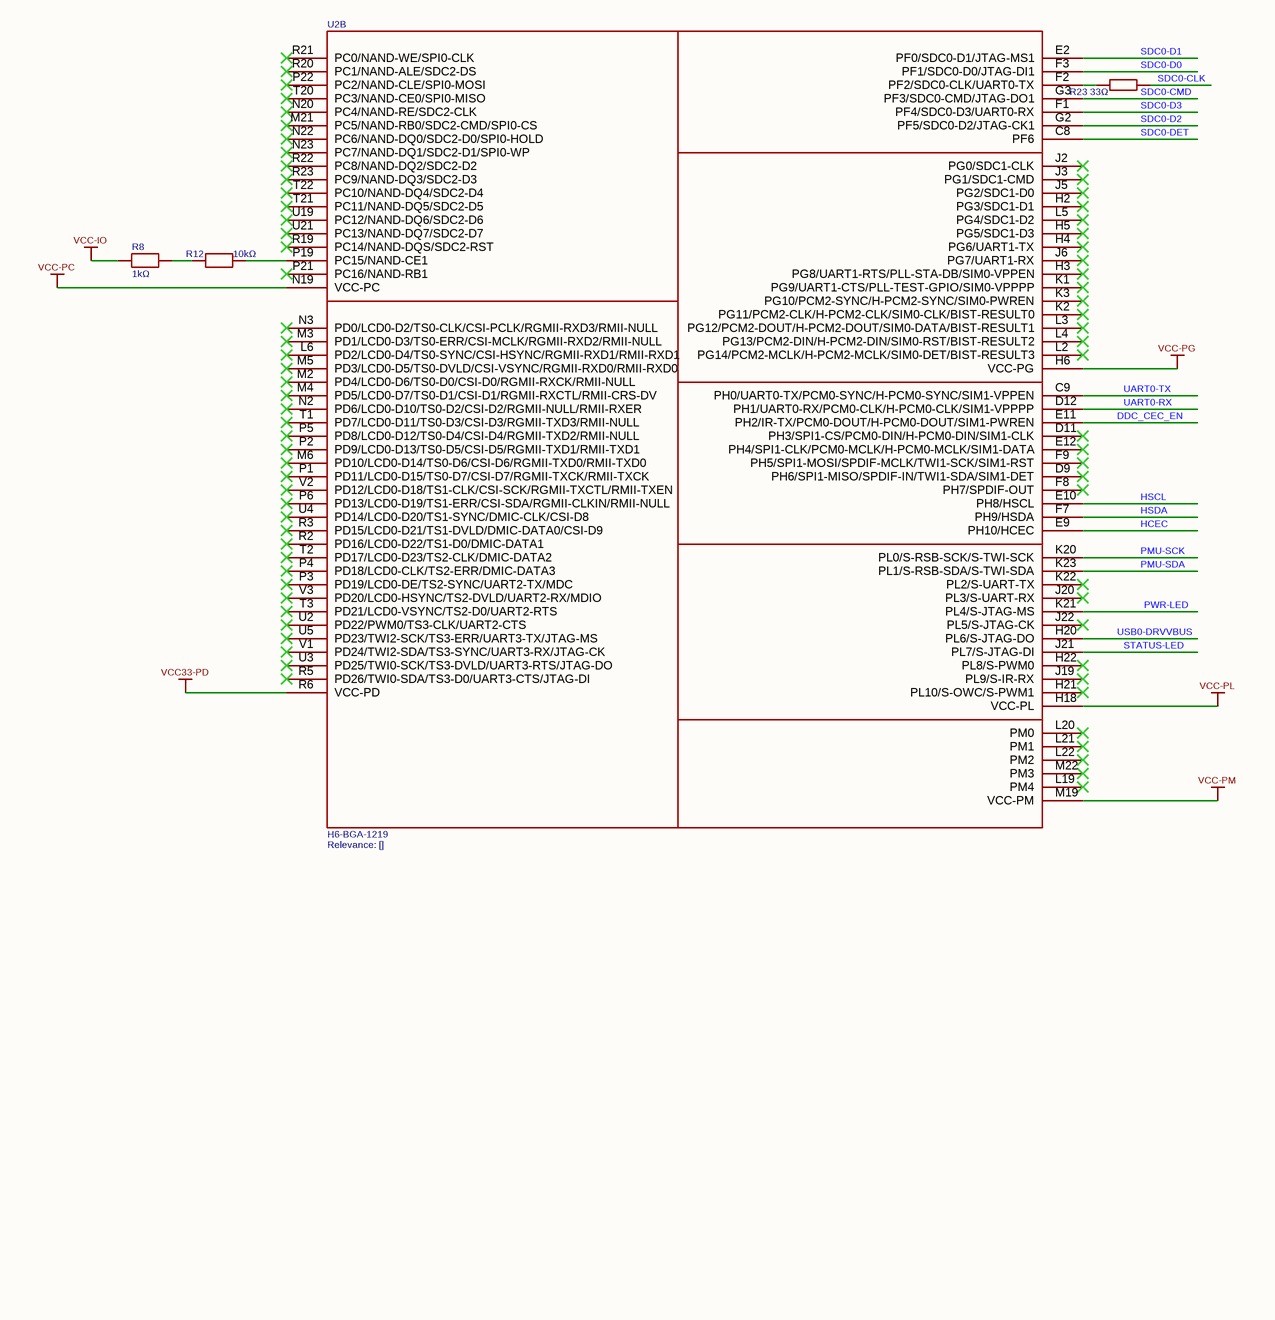
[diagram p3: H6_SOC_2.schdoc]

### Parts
R8  1kΩ  [R0805]
R12  10kΩ  [R0805]
R23  33Ω  [R0805]
U2  H6-BGA-1219  Relevance: []  [H6_BGA451]  (part B of 4)

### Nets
VCC33-PD: U2.R6(VCC-PD)  [project net CLDO2]
VCC-IO: R8.1  [project net CLDO1]
VCC-PC: U2.N19(VCC-PC)  [project net BLDO2]
VCC-PG: U2.H6(VCC-PG) U2.H18(VCC-PL) U2.M19(VCC-PM)  [also labelled VCC-PL, VCC-PM]  [project net ALDO1]
DDC_CEC_EN: U2.E11(PH2/IR-TX/PCM0-DOUT/H-PCM0-DOUT/SIM1-PWREN)
HCEC: U2.E9(PH10/HCEC)
HSCL: U2.E10(PH8/HSCL)
HSDA: U2.F7(PH9/HSDA)
PMU-SCK: U2.K20(PL0/S-RSB-SCK/S-TWI-SCK)
PMU-SDA: U2.K23(PL1/S-RSB-SDA/S-TWI-SDA)
PWR-LED: U2.K21(PL4/S-JTAG-MS)
SDC0-CLK: R23.2
SDC0-CMD: U2.G3(PF3/SDC0-CMD/JTAG-DO1)
SDC0-D0: U2.F3(PF1/SDC0-D0/JTAG-DI1)
SDC0-D1: U2.E2(PF0/SDC0-D1/JTAG-MS1)
SDC0-D2: U2.G2(PF5/SDC0-D2/JTAG-CK1)
SDC0-D3: U2.F1(PF4/SDC0-D3/UART0-RX)
SDC0-DET: U2.C8(PF6)
STATUS-LED: U2.J21(PL7/S-JTAG-DI)
UART0-RX: U2.D12(PH1/UART0-RX/PCM0-CLK/H-PCM0-CLK/SIM1-VPPPP)
UART0-TX: U2.C9(PH0/UART0-TX/PCM0-SYNC/H-PCM0-SYNC/SIM1-VPPEN)
USB0-DRVVBUS: U2.H20(PL6/S-JTAG-DO)
NetR8_2: R8.2 R12.1
NetR12_2: R12.2 U2.P19(PC15/NAND-CE1)
NetR23_1: R23.1 U2.F2(PF2/SDC0-CLK/UART0-TX)

Not connected (* = marked no-connect by the designer): U2 D9(PH6/SPI1-MISO/SPDIF-IN/TWI1-SDA/SIM1-DET)* D11(PH3/SPI1-CS/PCM0-DIN/H-PCM0-DIN/SIM1-CLK)* E12(PH4/SPI1-CLK/PCM0-MCLK/H-PCM0-MCLK/SIM1-DATA)* F8(PH7/SPDIF-OUT)* F9(PH5/SPI1-MOSI/SPDIF-MCLK/TWI1-SCK/SIM1-RST)* H2(PG3/SDC1-D1)* H3(PG8/UART1-RTS/PLL-STA-DB/SIM0-VPPEN)* H4(PG6/UART1-TX)* H5(PG5/SDC1-D3)* H21(PL10/S-OWC/S-PWM1)* H22(PL8/S-PWM0)* J2(PG0/SDC1-CLK)* J3(PG1/SDC1-CMD)* J5(PG2/SDC1-D0)* J6(PG7/UART1-RX)* J19(PL9/S-IR-RX)* J20(PL3/S-UART-RX)* J22(PL5/S-JTAG-CK)* K1(PG9/UART1-CTS/PLL-TEST-GPIO/SIM0-VPPPP)* K2(PG11/PCM2-CLK/H-PCM2-CLK/SIM0-CLK/BIST-RESULT0)* K3(PG10/PCM2-SYNC/H-PCM2-SYNC/SIM0-PWREN)* K22(PL2/S-UART-TX)* L2(PG14/PCM2-MCLK/H-PCM2-MCLK/SIM0-DET/BIST-RESULT3)* L3(PG12/PCM2-DOUT/H-PCM2-DOUT/SIM0-DATA/BIST-RESULT1)* L4(PG13/PCM2-DIN/H-PCM2-DIN/SIM0-RST/BIST-RESULT2)* L5(PG4/SDC1-D2)* L6(PD2/LCD0-D4/TS0-SYNC/CSI-HSYNC/RGMII-RXD1/RMII-RXD1)* L19(PM4)* L20(PM0)* L21(PM1)* L22(PM2)* M2(PD4/LCD0-D6/TS0-D0/CSI-D0/RGMII-RXCK/RMII-NULL)* M3(PD1/LCD0-D3/TS0-ERR/CSI-MCLK/RGMII-RXD2/RMII-NULL)* M4(PD5/LCD0-D7/TS0-D1/CSI-D1/RGMII-RXCTL/RMII-CRS-DV)* M5(PD3/LCD0-D5/TS0-DVLD/CSI-VSYNC/RGMII-RXD0/RMII-RXD0)* M6(PD10/LCD0-D14/TS0-D6/CSI-D6/RGMII-TXD0/RMII-TXD0)* M21(PC5/NAND-RB0/SDC2-CMD/SPI0-CS)* M22(PM3)* N2(PD6/LCD0-D10/TS0-D2/CSI-D2/RGMII-NULL/RMII-RXER)* N3(PD0/LCD0-D2/TS0-CLK/CSI-PCLK/RGMII-RXD3/RMII-NULL)* N20(PC4/NAND-RE/SDC2-CLK)* N22(PC6/NAND-DQ0/SDC2-D0/SPI0-HOLD)* N23(PC7/NAND-DQ1/SDC2-D1/SPI0-WP)* P1(PD11/LCD0-D15/TS0-D7/CSI-D7/RGMII-TXCK/RMII-TXCK)* P2(PD9/LCD0-D13/TS0-D5/CSI-D5/RGMII-TXD1/RMII-TXD1)* P3(PD19/LCD0-DE/TS2-SYNC/UART2-TX/MDC)* P4(PD18/LCD0-CLK/TS2-ERR/DMIC-DATA3)* P5(PD8/LCD0-D12/TS0-D4/CSI-D4/RGMII-TXD2/RMII-NULL)* P6(PD13/LCD0-D19/TS1-ERR/CSI-SDA/RGMII-CLKIN/RMII-NULL)* P21(PC16/NAND-RB1)* P22(PC2/NAND-CLE/SPI0-MOSI)* R2(PD16/LCD0-D22/TS1-D0/DMIC-DATA1)* R3(PD15/LCD0-D21/TS1-DVLD/DMIC-DATA0/CSI-D9)* R5(PD26/TWI0-SDA/TS3-D0/UART3-CTS/JTAG-DI)* R19(PC14/NAND-DQS/SDC2-RST)* R20(PC1/NAND-ALE/SDC2-DS)* R21(PC0/NAND-WE/SPI0-CLK)* R22(PC8/NAND-DQ2/SDC2-D2)* R23(PC9/NAND-DQ3/SDC2-D3)* T1(PD7/LCD0-D11/TS0-D3/CSI-D3/RGMII-TXD3/RMII-NULL)* T2(PD17/LCD0-D23/TS2-CLK/DMIC-DATA2)* T3(PD21/LCD0-VSYNC/TS2-D0/UART2-RTS)* T20(PC3/NAND-CE0/SPI0-MISO)* T21(PC11/NAND-DQ5/SDC2-D5)* T22(PC10/NAND-DQ4/SDC2-D4)* U2(PD22/PWM0/TS3-CLK/UART2-CTS)* U3(PD25/TWI0-SCK/TS3-DVLD/UART3-RTS/JTAG-DO)* U4(PD14/LCD0-D20/TS1-SYNC/DMIC-CLK/CSI-D8)* U5(PD23/TWI2-SCK/TS3-ERR/UART3-TX/JTAG-MS)* U19(PC12/NAND-DQ6/SDC2-D6)* U21(PC13/NAND-DQ7/SDC2-D7)* V1(PD24/TWI2-SDA/TS3-SYNC/UART3-RX/JTAG-CK)* V2(PD12/LCD0-D18/TS1-CLK/CSI-SCK/RGMII-TXCTL/RMII-TXEN)* V3(PD20/LCD0-HSYNC/TS2-DVLD/UART2-RX/MDIO)*

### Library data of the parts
R8 = FRC0805F1001TS: 电阻类型:厚膜电阻;阻值:1kΩ;精度:±1%;功率:125mW;工作电压:150V;温度系数:±100ppm/℃;; Manufacturer: FOJAN(富捷); 3D Model: 37a81e68749a4138bd2dfa6897b24b85¦0819f05c4eef4c71ace90d822a990e87; 3D Model Transform: 78.74,51.181,0,0,0,0,0,-0.0005,0; Tolerance: ±1%; Power(Watts): 125mW; Voltage-Supply(Max): 150V; AddInBom: yes; ModelName: R0805_L2.0-W1.3-H0.6
R12 = FRC0805F1002TS: 电阻类型:厚膜电阻;阻值:10kΩ;精度:±1%;功率:125mW;工作电压:150V;温度系数:±100ppm/℃;; Manufacturer: FOJAN(富捷); AddInBom: yes; ModelId: 37a81e68749a4138bd2dfa6897b24b85¦0819f05c4eef4c71ace90d822a990e87; ModelName: R0805_L2.0-W1.3-H0.6; ModelTransform: 78.74,51.181,0,0,0,0,0,-0.0005,0; Tolerance: ±1%; Power(Watts): 125mW; Voltage-Supply(Max): 150V
R23 = 0805W8F330JT5E: 电阻类型:厚膜电阻;阻值:33Ω;精度:±1%;功率:125mW;工作电压:150V;温度系数:±200ppm/℃;; Manufacturer: UNI-ROYAL(厚声); AddInBom: yes; ModelId: 37a81e68749a4138bd2dfa6897b24b85¦0819f05c4eef4c71ace90d822a990e87; ModelName: R0805_L2.0-W1.3-H0.6; ModelTransform: 78.74,51.181,0,0,0,0,0,-0.0005,0; Tolerance: ±1%; Power(Watts): 125mW; Voltage-Supply(Max): 150V
U2 = H6-BGA-1219: Value: 1; SPLIT_INST: TRUE; SWAP_INFO: (S1+S2+S3+S4); componentDisplayMode: -1; AddInBom: yes; OriginFootprint: BGA451P65B1500_1500H118

## Sheet H6_SOC_1.schdoc
size 420 x 297 mm; Device: Drawing-Symbol_A4; @Board Name: Board1_1; @Page Name: H6_SOC_1; @Create Time: 13:52:28; @Page Count: 7; @Page No: 2; @Schematic Name: Schematic1_1; @Update Time: 13:52:28; @Assembly Variant: Basic; Border: 1; Title Block Position: 3; Size: A4; Region Start: 1; X Region Count: 6; Y Region Count: 4; Blade Width: 10; Width: 1655; Height: 1170; Symbol: Drawing-Symbol_A4; Company: 嘉立创EDA; Version: V1.0; Page Size: A4; @Project Name: N01｜全志 H6 Linux 主板; @Update Date: 2026-11-21; @Create Date: 2026-11-21
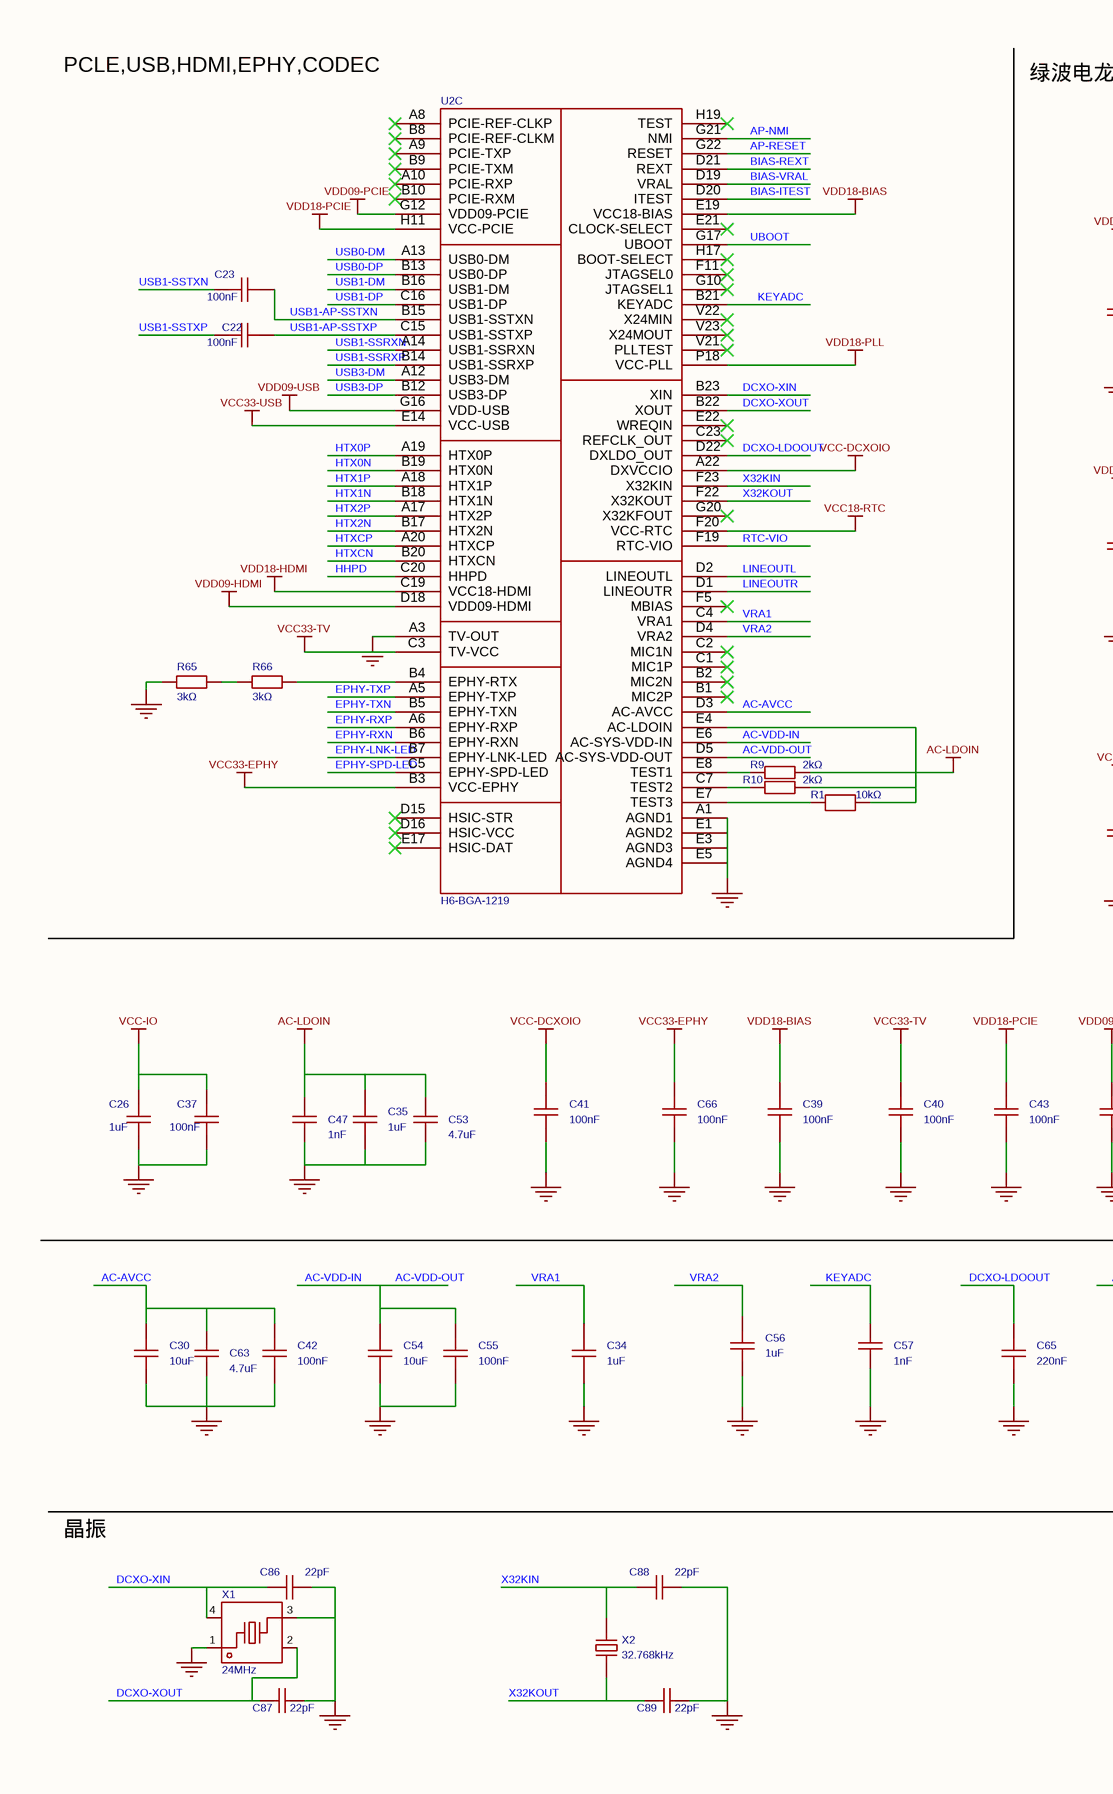
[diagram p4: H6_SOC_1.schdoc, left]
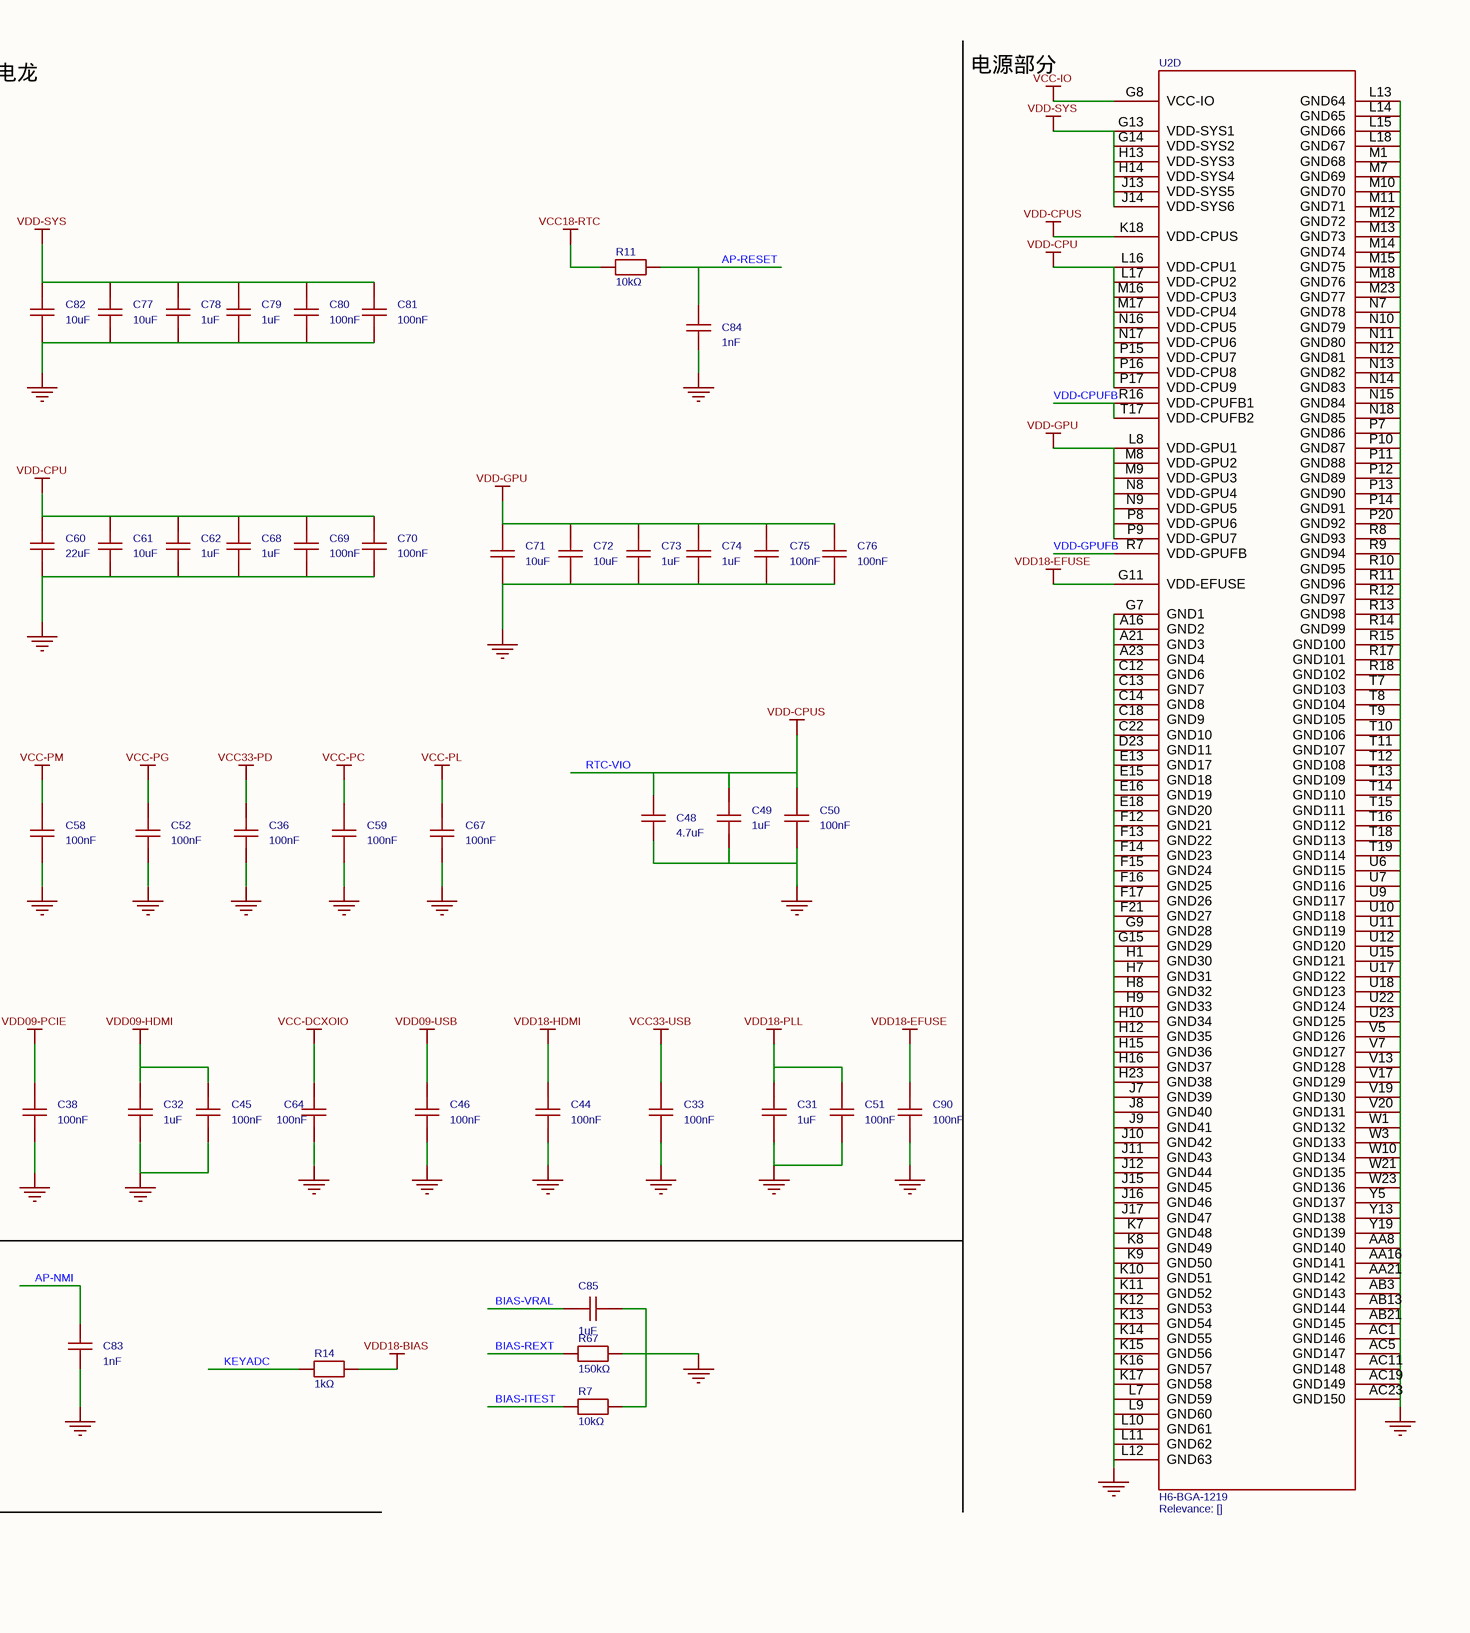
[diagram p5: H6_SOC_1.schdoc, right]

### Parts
C22  100nF  [C0402]
C23  100nF  [C0402]
C26  1uF  [C0402]
C30  10uF  [C0603]
C31  1uF  [C0402]
C32  1uF  [C0402]
C33  100nF  [C0402]
C34  1uF  [C0402]
C35  1uF  [C0402]
C36  100nF  [C0402]
C37  100nF  [C0402]
C38  100nF  [C0402]
C39  100nF  [C0402]
C40  100nF  [C0402]
C41  100nF  [C0402]
C42  100nF  [C0402]
C43  100nF  [C0402]
C44  100nF  [C0402]
C45  100nF  [C0402]
C46  100nF  [C0402]
C47  1nF  [C0402]
C48  4.7uF  [C0603]
C49  1uF  [C0402]
C50  100nF  [C0402]
C51  100nF  [C0402]
C52  100nF  [C0402]
C53  4.7uF  [C0603]
C54  10uF  [C0603]
C55  100nF  [C0402]
C56  1uF  [C0402]
C57  1nF  [C0402]
C58  100nF  [C0402]
C59  100nF  [C0402]
C60  22uF  [C0603]
C61  10uF  [C0603]
C62  1uF  [C0402]
C63  4.7uF  [C0603]
C64  100nF  [C0402]
C65  220nF  [C0402]
C66  100nF  [C0402]
C67  100nF  [C0402]
C68  1uF  [C0402]
C69  100nF  [C0402]
C70  100nF  [C0402]
C71  10uF  [C0603]
C72  10uF  [C0603]
C73  1uF  [C0402]
C74  1uF  [C0402]
C75  100nF  [C0402]
C76  100nF  [C0402]
C77  10uF  [C0603]
C78  1uF  [C0402]
C79  1uF  [C0402]
C80  100nF  [C0402]
C81  100nF  [C0402]
C82  10uF  [C0603]
C83  1nF  [C0402]
C84  1nF  [C0402]
C85  1uF  [C0402]
C86  22pF  [C0402]
C87  22pF  [C0402]
C88  22pF  [C0402]
C89  22pF  [C0402]
C90  100nF  [C0402]
R1  10kΩ  [R0805]
R7  10kΩ  [R0805]
R9  2kΩ  [R0805]
R10  2kΩ  [R0805]
R11  10kΩ  [R0805]
R14  1kΩ  [R0805]
R65  3kΩ  [R0805]
R66  3kΩ  [R0805]
R67  150kΩ  [R0805]
U2  H6-BGA-1219  [H6_BGA451]  (parts C,D of 4)
X1  24MHz  [CRYSTAL-SMD_4P-L3.2-W2.5-BL]
X2  32.768kHz  [OSC-SMD_L3.2-W1.5]

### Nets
AC-LDOIN: C35.2 C40.2 C47.2 C53.2 C66.2 R1.2 R9.2 R10.2 U2.B3(VCC-EPHY) U2.C3(TV-VCC) U2.E4(AC-LDOIN)  [also labelled VCC33-EPHY, VCC33-TV]  [project net ALDO2]
GND: C26.1 C30.1 C31.1 C32.1 C33.1 C34.1 C35.1 C36.1 C37.1 C38.1 C39.1 C40.1 C41.1 C42.1 C43.1 C44.1 C45.1 C46.1 C47.1 C48.1 C49.1 C50.1 C51.1 C52.1 C53.1 C54.1 C55.1 C56.1 C57.1 C58.1 C59.1 C60.1 C61.1 C62.1 C63.1 C64.1 C65.1 C66.1 C67.1 C68.1 C69.1 C70.1 C71.1 C72.1 C73.1 C74.1 C75.1 C76.1 C77.1 C78.1 C79.1 C80.1 C81.1 C82.1 C83.1 C84.1 C85.1 C86.2 C87.2 C88.2 C89.2 C90.1 R7.2 R65.1 R67.2 U2.A1(AGND1) U2.A3(TV-OUT) U2.A16(GND2) U2.A21(GND3) U2.A23(GND4) U2.AA8(GND140) U2.AA16(GND141) U2.AA21(GND142) U2.AB3(GND143) U2.AB13(GND144) U2.AB21(GND145) U2.AC1(GND146) U2.AC5(GND147) U2.AC11(GND148) U2.AC19(GND149) U2.AC23(GND150) U2.C12(GND6) U2.C13(GND7) U2.C14(GND8) U2.C18(GND9) U2.C22(GND10) U2.D23(GND11) U2.E1(AGND2) U2.E3(AGND3) U2.E5(AGND4) U2.E13(GND17) U2.E15(GND18) U2.E16(GND19) U2.E18(GND20) U2.F12(GND21) U2.F13(GND22) U2.F14(GND23) U2.F15(GND24) U2.F16(GND25) U2.F17(GND26) U2.F21(GND27) U2.G7(GND1) U2.G9(GND28) U2.G15(GND29) U2.H1(GND30) U2.H7(GND31) U2.H8(GND32) U2.H9(GND33) U2.H10(GND34) U2.H12(GND35) U2.H15(GND36) U2.H16(GND37) U2.H23(GND38) U2.J7(GND39) U2.J8(GND40) U2.J9(GND41) U2.J10(GND42) U2.J11(GND43) U2.J12(GND44) U2.J15(GND45) U2.J16(GND46) U2.J17(GND47) U2.K7(GND48) U2.K8(GND49) U2.K9(GND50) U2.K10(GND51) U2.K11(GND52) U2.K12(GND53) U2.K13(GND54) U2.K14(GND55) U2.K15(GND56) U2.K16(GND57) U2.K17(GND58) U2.L7(GND59) U2.L9(GND60) U2.L10(GND61) U2.L11(GND62) U2.L12(GND63) U2.L13(GND64) U2.L14(GND65) U2.L15(GND66) U2.L18(GND67) U2.M1(GND68) U2.M7(GND69) U2.M10(GND70) U2.M11(GND71) U2.M12(GND72) U2.M13(GND73) U2.M14(GND74) U2.M15(GND75) U2.M18(GND76) U2.M23(GND77) U2.N7(GND78) U2.N10(GND79) U2.N11(GND80) U2.N12(GND81) U2.N13(GND82) U2.N14(GND83) U2.N15(GND84) U2.N18(GND85) U2.P7(GND86) U2.P10(GND87) U2.P11(GND88) U2.P12(GND89) U2.P13(GND90) U2.P14(GND91) U2.P20(GND92) U2.R8(GND93) U2.R9(GND94) U2.R10(GND95) U2.R11(GND96) U2.R12(GND97) U2.R13(GND98) U2.R14(GND99) U2.R15(GND100) U2.R17(GND101) U2.R18(GND102) U2.T7(GND103) U2.T8(GND104) U2.T9(GND105) U2.T10(GND106) U2.T11(GND107) U2.T12(GND108) U2.T13(GND109) U2.T14(GND110) U2.T15(GND111) U2.T16(GND112) U2.T18(GND113) U2.T19(GND114) U2.U6(GND115) U2.U7(GND116) U2.U9(GND117) U2.U10(GND118) U2.U11(GND119) U2.U12(GND120) U2.U15(GND121) U2.U17(GND122) U2.U18(GND123) U2.U22(GND124) U2.U23(GND125) U2.V5(GND126) U2.V7(GND127) U2.V13(GND128) U2.V17(GND129) U2.V19(GND130) U2.V20(GND131) U2.W1(GND132) U2.W3(GND133) U2.W10(GND134) U2.W21(GND135) U2.W23(GND136) U2.Y5(GND137) U2.Y13(GND138) U2.Y19(GND139) X1.1 X1.3
RTC-VIO: C48.2 C49.2 C50.2 U2.F19(RTC-VIO) U2.K18(VDD-CPUS)  [also labelled VDD-CPUS]
VCC18-RTC: R11.1 U2.F20(VCC-RTC)
VCC33-PD: C36.2  [project net CLDO2]
VCC-DCXOIO: C41.2 C52.2 C58.2 C64.2 C67.2 U2.A22(DXVCCIO)  [also labelled VCC-PG, VCC-PL, VCC-PM]  [project net ALDO1]
VCC-IO: C26.2 C33.2 C37.2 U2.E14(VCC-USB) U2.G8(VCC-IO)  [also labelled VCC33-USB]  [project net CLDO1]
VCC-PC: C43.2 C44.2 C59.2 C90.2 U2.C19(VCC18-HDMI) U2.G11(VDD-EFUSE) U2.H11(VCC-PCIE)  [also labelled VDD18-EFUSE, VDD18-HDMI, VDD18-PCIE]  [project net BLDO2]
VDD18-BIAS: C31.2 C39.2 C51.2 R14.2 U2.E19(VCC18-BIAS) U2.P18(VCC-PLL)  [also labelled VDD18-PLL]  [project net BLDO1]
VDD-CPU: C60.2 C61.2 C62.2 C68.2 C69.2 C70.2 U2.L16(VDD-CPU1) U2.L17(VDD-CPU2) U2.M16(VDD-CPU3) U2.M17(VDD-CPU4) U2.N16(VDD-CPU5) U2.N17(VDD-CPU6) U2.P15(VDD-CPU7) U2.P16(VDD-CPU8) U2.P17(VDD-CPU9)
VDD-GPU: C71.2 C72.2 C73.2 C74.2 C75.2 C76.2 U2.L8(VDD-GPU1) U2.M8(VDD-GPU2) U2.M9(VDD-GPU3) U2.N8(VDD-GPU4) U2.N9(VDD-GPU5) U2.P8(VDD-GPU6) U2.P9(VDD-GPU7)
VDD-SYS: C32.2 C38.2 C45.2 C46.2 C77.2 C78.2 C79.2 C80.2 C81.2 C82.2 U2.D18(VDD09-HDMI) U2.G12(VDD09-PCIE) U2.G13(VDD-SYS1) U2.G14(VDD-SYS2) U2.G16(VDD-USB) U2.H13(VDD-SYS3) U2.H14(VDD-SYS4) U2.J13(VDD-SYS5) U2.J14(VDD-SYS6)  [also labelled VDD09-HDMI, VDD09-PCIE, VDD09-USB]  [project net DCDCD]
AC-AVCC: C30.2 C42.2 C63.2 U2.D3(AC-AVCC)
AC-VDD-IN: C54.2 C55.2 U2.D5(AC-SYS-VDD-OUT) U2.E6(AC-SYS-VDD-IN)  [also labelled AC-VDD-OUT]
AP-NMI: C83.2 U2.G21(NMI)
AP-RESET: C84.2 R11.2 U2.G22(RESET)
BIAS-ITEST: R7.1 U2.D20(ITEST)
BIAS-REXT: R67.1 U2.D21(REXT)
BIAS-VRAL: C85.2 U2.D19(VRAL)
DCXO-LDOOUT: C65.2 U2.D22(DXLDO_OUT)
DCXO-XIN: C86.1 U2.B23(XIN) X1.4(GND)
DCXO-XOUT: C87.1 U2.B22(XOUT) X1.2(GND)
EPHY-LNK-LED: U2.B7(EPHY-LNK-LED)
EPHY-RXN: U2.B6(EPHY-RXN)
EPHY-RXP: U2.A6(EPHY-RXP)
EPHY-SPD-LED: U2.C5(EPHY-SPD-LED)
EPHY-TXN: U2.B5(EPHY-TXN)
EPHY-TXP: U2.A5(EPHY-TXP)
HHPD: U2.C20(HHPD)
HTX0N: U2.B19(HTX0N)
HTX0P: U2.A19(HTX0P)
HTX1N: U2.B18(HTX1N)
HTX1P: U2.A18(HTX1P)
HTX2N: U2.B17(HTX2N)
HTX2P: U2.A17(HTX2P)
HTXCN: U2.B20(HTXCN)
HTXCP: U2.A20(HTXCP)
KEYADC: C57.2 R14.1 U2.B21(KEYADC)
LINEOUTL: U2.D2(LINEOUTL)
LINEOUTR: U2.D1(LINEOUTR)
UBOOT: U2.G17(UBOOT)
USB0-DM: U2.A13(USB0-DM)
USB0-DP: U2.B13(USB0-DP)
USB1-AP-SSTXN: C23.1 U2.B15(USB1-SSTXN)
USB1-AP-SSTXP: C22.1 U2.C15(USB1-SSTXP)
USB1-DM: U2.B16(USB1-DM)
USB1-DP: U2.C16(USB1-DP)
USB1-SSRXN: U2.A14(USB1-SSRXN)
USB1-SSRXP: U2.B14(USB1-SSRXP)
USB1-SSTXN: C23.2
USB1-SSTXP: C22.2
USB3-DM: U2.A12(USB3-DM)
USB3-DP: U2.B12(USB3-DP)
VDD-CPUFB: U2.R16(VDD-CPUFB1) U2.T17(VDD-CPUFB2)
VDD-GPUFB: U2.R7(VDD-GPUFB)
VRA1: C34.2 U2.C4(VRA1)
VRA2: C56.2 U2.D4(VRA2)
X32KIN: C88.1 U2.F23(X32KIN) X2.2
X32KOUT: C89.1 U2.F22(X32KOUT) X2.1
NetR1_1: R1.1 U2.E7(TEST3)
NetR9_1: R9.1 U2.E8(TEST1)
NetR10_1: R10.1 U2.C7(TEST2)
NetR65_2: R65.2 R66.1
NetR66_2: R66.2 U2.B4(EPHY-RTX)

Not connected (* = marked no-connect by the designer): U2 A8(PCIE-REF-CLKP)* A9(PCIE-TXP)* A10(PCIE-RXP)* B1(MIC2P)* B2(MIC2N)* B8(PCIE-REF-CLKM)* B9(PCIE-TXM)* B10(PCIE-RXM)* C1(MIC1P)* C2(MIC1N)* C23(REFCLK_OUT)* D15(HSIC-STR)* D16(HSIC-VCC)* E17(HSIC-DAT)* E21(CLOCK-SELECT)* E22(WREQIN)* F5(MBIAS)* F11(JTAGSEL0)* G10(JTAGSEL1)* G20(X32KFOUT)* H17(BOOT-SELECT)* H19(TEST)* V21(PLLTEST)* V22(X24MIN)* V23(X24MOUT)*

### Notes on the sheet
- PCLE,USB,HDMI,EPHY,CODEC
- 绿波电龙
- 电源部分
- 晶振

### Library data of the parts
C22 C23 = CL05B104KO5NNNC: as C126 on sheet SD,USB,CODEC
C26 C31 C32 C34 C35 C49 C56 C62 C68 C73 C74 C78 C79 C85 = HGC0402R5105K500NTEJ: 容值:1uF;精度:±10%;额定电压:50V;温度系数:X5R;; Manufacturer: Chinocera(华瓷); AddInBom: yes; ModelId: 36a51122f27c49738f86b3bfa98863e0¦0819f05c4eef4c71ace90d822a990e87; ModelName: C0402_L1.0-W0.5-H0.5; ModelTransform: 39.37,19.685,0,0,0,0,0,0,0; Tolerance: ±10%; Voltage Rating: 50V; Temperature Coefficient: X5R
C30 C54 C61 C71 C72 C77 C82 = FCC0603X106K100CT: as C93 on sheet Lpddr3
C33 C36-C46 C50-C52 C55 C58 C59 C64 C66 C67 C69 C70 C75 C76 C80 C81 C90 = CL05B104KO5NNNC: 容值:100nF;精度:±10%;额定电压:16V;温度系数:X7R;; Manufacturer: SAMSUNG(三星); AddInBom: yes; ModelId: 36a51122f27c49738f86b3bfa98863e0¦0819f05c4eef4c71ace90d822a990e87; ModelName: C0402_L1.0-W0.5-H0.5; ModelTransform: 39.37,19.685,0,0,0,0,0,0,0; Tolerance: ±10%; Voltage Rating: 16V; Temperature Coefficient: X7R
C47 C57 C83 C84 = CC0402KRX7R9BB102: 容值:1nF;精度:±10%;额定电压:50V;材质(温度系数):X7R;; Manufacturer: YAGEO(国巨); AddInBom: yes; ModelId: 36a51122f27c49738f86b3bfa98863e0¦0819f05c4eef4c71ace90d822a990e87; ModelName: C0402_L1.0-W0.5-H0.5; ModelTransform: 39.37,19.685,0,0,0,0,0,0,0; Tolerance: ±10%; Voltage Rated: 50V; Temperature Coefficient: X7R
C48 C53 C63 = CL10A475KP8NNNC: 容值:4.7uF;精度:±10%;额定电压:10V;温度系数:X5R;; Manufacturer: SAMSUNG(三星); AddInBom: yes; ModelId: ac125912035d415993ca9572d50418b1¦0819f05c4eef4c71ace90d822a990e87; ModelName: C0603_L1.6-W0.8-H0.8; ModelTransform: 62.992,31.496,0,0,0,0,0,0,0; Tolerance: ±10%; Voltage Rating: 10V; Temperature Coefficient: X5R
C60 = HGC0603R5226M100NTHJ: 容值:22uF;精度:±20%;额定电压:10V;温度系数:X5R;; Manufacturer: Chinocera(华瓷); AddInBom: yes; ModelId: ac125912035d415993ca9572d50418b1¦0819f05c4eef4c71ace90d822a990e87; ModelName: C0603_L1.6-W0.8-H0.8; ModelTransform: 62.992,31.496,0,0,0,0,0,0,0; Tolerance: ±20%; Voltage Rating: 10V; Temperature Coefficient: X5R
C65 = GRM155R61H224KE01D: 容值:220nF;精度:±10%;额定电压:50V;温度系数:X5R;; Manufacturer: muRata(村田); 3D Model: 36a51122f27c49738f86b3bfa98863e0¦0819f05c4eef4c71ace90d822a990e87; 3D Model Transform: 39.37,19.685,0,0,0,0,0,0,0; Tolerance: ±10%; Voltage Rating: 50V; Temperature Coefficient: X5R; AddInBom: yes; ModelName: C0402_L1.0-W0.5-H0.5
C86-C89 = CC0402JRNPO9BN220: 容值:22pF;精度:±5%;额定电压:50V;温度系数:NP0;; Manufacturer: YAGEO(国巨); AddInBom: yes; ModelId: 36a51122f27c49738f86b3bfa98863e0¦0819f05c4eef4c71ace90d822a990e87; ModelName: C0402_L1.0-W0.5-H0.5; ModelTransform: 39.37,19.685,0,0,0,0,0,0,0; Tolerance: ±5%; Voltage Rating: 50V; Temperature Coefficient: NP0
R1 R7 R11 = FRC0805F1002TS: 电阻类型:厚膜电阻;阻值:10kΩ;精度:±1%;功率:125mW;工作电压:150V;温度系数:±100ppm/℃;; Manufacturer: FOJAN(富捷); 3D Model: 37a81e68749a4138bd2dfa6897b24b85¦0819f05c4eef4c71ace90d822a990e87; 3D Model Transform: 78.74,51.181,0,0,0,0,0,-0.0005,0; Tolerance: ±1%; Power(Watts): 125mW; Voltage-Supply(Max): 150V; AddInBom: yes; ModelName: R0805_L2.0-W1.3-H0.6
R9 R10 = RC0805FR-072KL: 电阻类型:厚膜电阻;阻值:2kΩ;精度:±1%;功率:125mW;最大工作电压:150V;温度系数:±100ppm/℃;; Manufacturer: YAGEO(国巨); 3D Model: 37a81e68749a4138bd2dfa6897b24b85¦0819f05c4eef4c71ace90d822a990e87; 3D Model Transform: 78.74,51.181,0,0,0,0,0,-0.0005,0; Tolerance: ±1%; Power(Watts): 125mW; Overload Voltage (Max): 150V; AddInBom: yes; ModelName: R0805_L2.0-W1.3-H0.6
R14 = FRC0805F1001TS: as R8 on sheet H6_SOC_2
R65 R66 = 0805W8F3001T5E: 电阻类型:厚膜电阻;阻值:3kΩ;精度:±1%;功率:125mW;工作电压:150V;温度系数:±100ppm/℃;; Manufacturer: UNI-ROYAL(厚声); AddInBom: yes; ModelId: 37a81e68749a4138bd2dfa6897b24b85¦0819f05c4eef4c71ace90d822a990e87; ModelName: R0805_L2.0-W1.3-H0.6; ModelTransform: 78.74,51.181,0,0,0,0,0,-0.0005,0; Tolerance: ±1%; Power(Watts): 125mW; Voltage-Supply(Max): 150V
R67 = FRC0805F1503TS: 电阻类型:厚膜电阻;阻值:150kΩ;精度:±1%;功率:125mW;工作电压:150V;温度系数:±100ppm/℃;; Manufacturer: FOJAN(富捷); AddInBom: yes; ModelId: 37a81e68749a4138bd2dfa6897b24b85¦0819f05c4eef4c71ace90d822a990e87; ModelName: R0805_L2.0-W1.3-H0.6; ModelTransform: 78.74,51.181,0,0,0,0,0,-0.0005,0; Tolerance: ±1%; Power(Watts): 125mW; Voltage-Supply(Max): 150V
U2 = H6-BGA-1219: as U2 on sheet Lpddr3
X1 = XL2EL89COI-111YLC-24M: 晶振类型:贴片晶振;频率:24MHz;常温频差:±10ppm;负载电容:12pF;频率稳定度:±20ppm;; Manufacturer: YXC(扬兴晶振); AddInBom: yes; ModelId: ff2dfd5650294453a14147960efe1838¦0819f05c4eef4c71ace90d822a990e87; ModelTransform: 125.984,98.425,0,0,0,0,0,0,0; Normal temperature Frequency Tolerance: ±10ppm; Load Capacitance: 12pF; Frequency Stability: ±20ppm
X2 = X321532768KGD2SI: 晶振类型:贴片晶振;频率:32.768kHz;常温频差:±20ppm;负载电容:12.5pF;频率稳定度:±30ppm;; Manufacturer: YXC(扬兴晶振); AddInBom: yes; ModelId: 2dd241c0893b4675b8def6f6998a8251¦0819f05c4eef4c71ace90d822a990e87; ModelName: OSC-SMD_L3.2-W1.5-H0.8; ModelTransform: 125.984,59.055,0,0,0,0,0,0,0; Normal temperature Frequency Tolerance: ±20ppm; Load Capacitance: 12.5pF; Frequency Stability: ±30ppm; Equivalent Series Resistance(ESR): 70kΩ

## Sheet Power_Tree_1.schdoc
size 297 x 209 mm; Symbol: Drawing-Symbol_A4; Company: 嘉立创EDA; Version: V1.0; Page Size: A4; @Project Name: N01｜全志 H6 Linux 主板; @Update Date: 2026-11-21; @Create Date: 2026-11-21; Device: Drawing-Symbol_A4; @Board Name: Board1_1; @Page Name: Power_Tree_1; @Create Time: 13:52:28; @Page Count: 7; @Page No: 1; @Schematic Name: Schematic1_1; @Update Time: 13:52:28; @Assembly Variant: Basic; Border: 1; Title Block Position: 3; Size: A4; Width: 1170; Height: 825; Region Start: 1; X Region Count: 6; Y Region Count: 4; Blade Width: 10
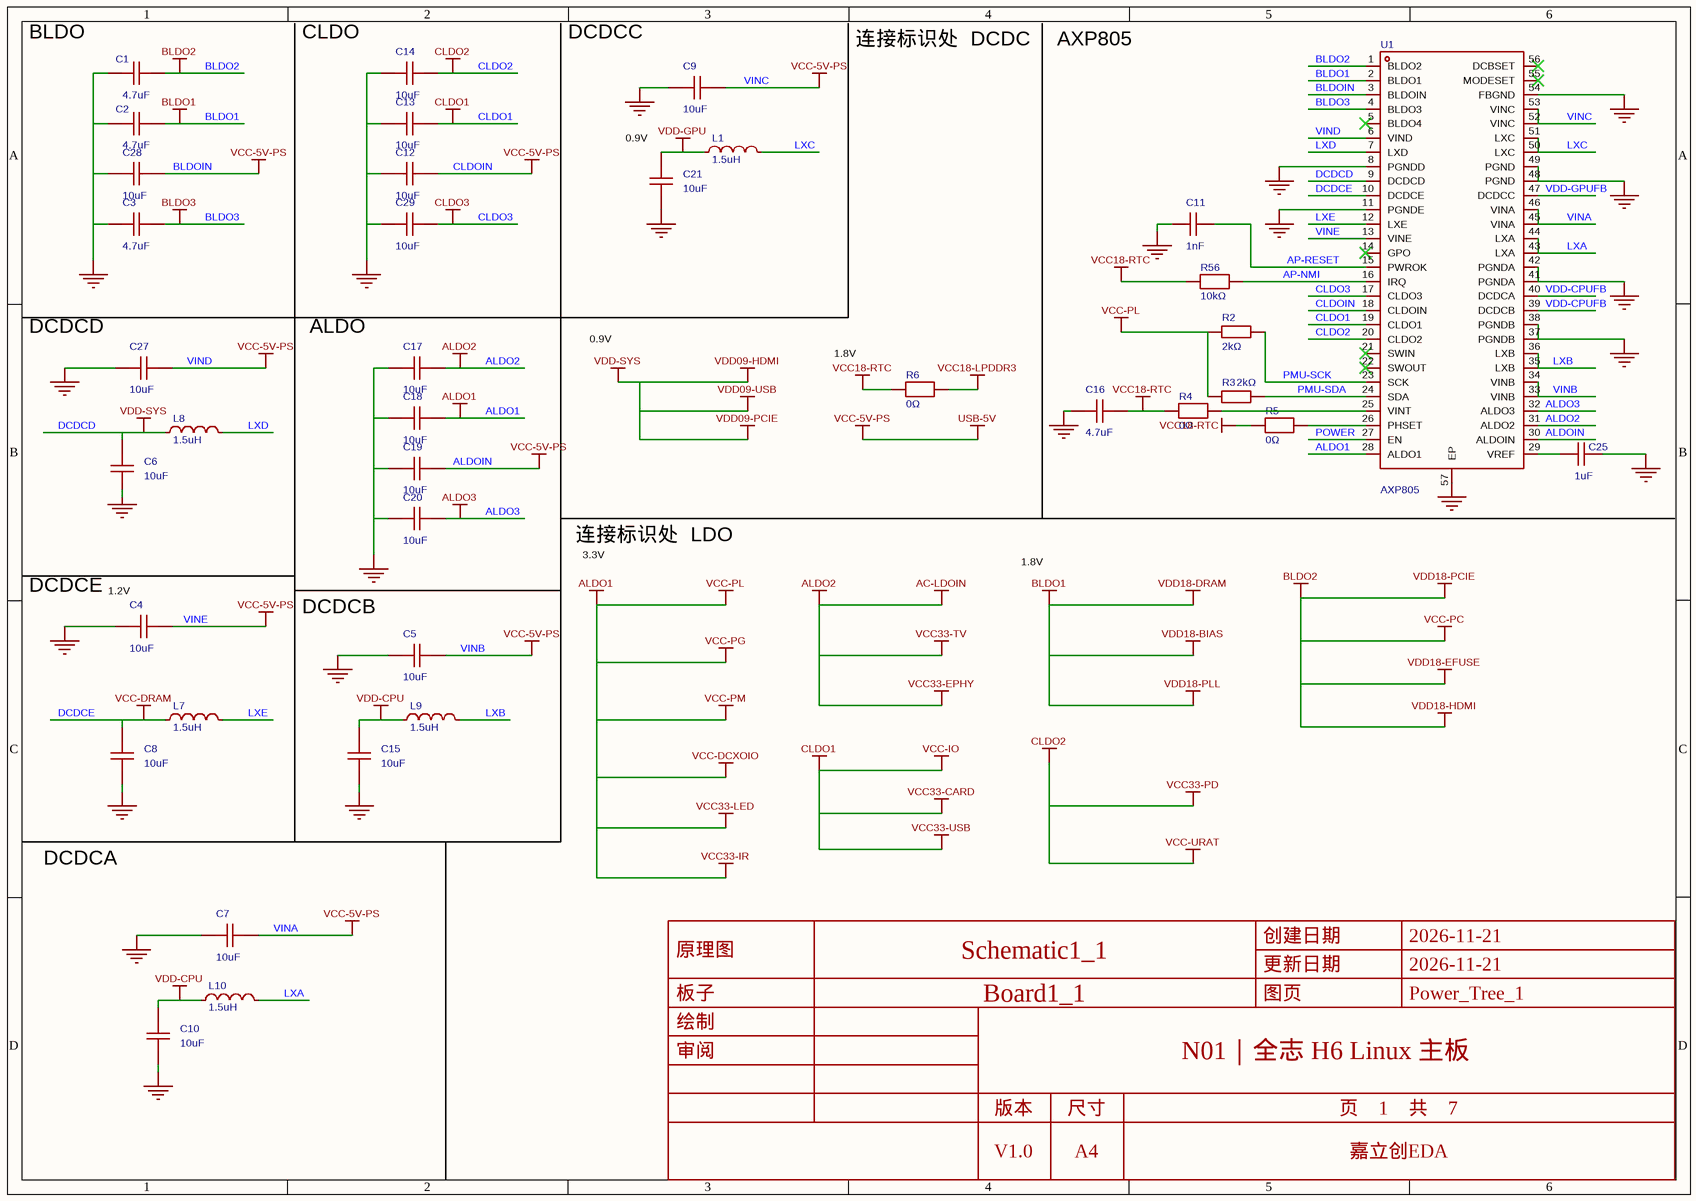
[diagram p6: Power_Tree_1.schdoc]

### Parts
C1  4.7uF  [C0603]
C2  4.7uF  [C0603]
C3  4.7uF  [C0603]
C4  10uF  [C0603]
C5  10uF  [C0603]
C6  10uF  [C0603]
C7  10uF  [C0603]
C8  10uF  [C0603]
C9  10uF  [C0603]
C10  10uF  [C0603]
C11  1nF  [C0603]
C12  10uF  [C0603]
C13  10uF  [C0603]
C14  10uF  [C0603]
C15  10uF  [C0603]
C16  4.7uF  [C0603]
C17  10uF  [C0603]
C18  10uF  [C0603]
C19  10uF  [C0603]
C20  10uF  [C0603]
C21  10uF  [C0603]
C25  1uF  [C0603]
C27  10uF  [C0603]
C28  10uF  [C0603]
C29  10uF  [C0603]
L1  1.5uH  [IND-SMD_L4.4-W4.2]
L7  1.5uH  [IND-SMD_L4.4-W4.2]
L8  1.5uH  [IND-SMD_L4.4-W4.2]
L9  1.5uH  [IND-SMD_L4.4-W4.2]
L10  1.5uH  [IND-SMD_L4.4-W4.2]
R2  2kΩ  [R0805]
R3  2kΩ  [R0805]
R4  0Ω  [R0805]
R5  0Ω  [R0805]
R6  0Ω  [R0805]
R56  10kΩ  [R0805]
U1  AXP805  [QFN-56_L7.0-W7.0-P0.40-TL-EP5.2]

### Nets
ALDO1: C18.2 R2.1 R3.1 U1.28(ALDO1)  [also labelled VCC-DCXOIO, VCC-PG, VCC-PL, VCC-PM, VCC33-IR, VCC33-LED]
ALDO2: C17.2 U1.31(ALDO2)  [also labelled AC-LDOIN, VCC33-EPHY, VCC33-TV]
ALDO3: C20.2 U1.32(ALDO3)
ALDOIN: C4.2 C5.2 C7.2 C9.2 C12.2 C19.2 C27.2 C28.2 U1.3(BLDOIN) U1.6(VIND) U1.13(VINE) U1.18(CLDOIN) U1.30(ALDOIN) U1.33(VINB) U1.34(VINB) U1.45(VINA) U1.46(VINA) U1.52(VINC) U1.53(VINC)  [also labelled BLDOIN, CLDOIN, USB-5V, VCC-5V-PS, VINA, VINB, VINC, VIND, VINE]
BLDO1: C2.2 U1.2(BLDO1)  [also labelled VDD18-BIAS, VDD18-DRAM, VDD18-PLL]
BLDO2: C1.2 U1.1(BLDO2)  [also labelled VCC-PC, VDD18-EFUSE, VDD18-HDMI, VDD18-PCIE]
BLDO3: C3.2 U1.4(BLDO3)
CLDO1: C13.2 U1.19(CLDO1)  [also labelled VCC-IO, VCC33-CARD, VCC33-USB]
CLDO2: C14.2 U1.20(CLDO2)  [also labelled VCC-URAT, VCC33-PD]
CLDO3: C29.2 U1.17(CLDO3)
DCDCD: C6.2 L8.1 U1.9(DCDCD)  [also labelled VDD-SYS, VDD09-HDMI, VDD09-PCIE, VDD09-USB]
DCDCE: C8.2 L7.1 U1.10(DCDCE)  [also labelled VCC-DRAM]
GND: C1.1 C2.1 C3.1 C4.1 C5.1 C6.1 C7.1 C8.1 C9.1 C10.1 C11.1 C12.1 C13.1 C14.1 C15.1 C16.1 C17.1 C18.1 C19.1 C20.1 C21.1 C25.2 C27.1 C28.1 C29.1 U1.8(PGNDD) U1.11(PGNDE) U1.37(PGNDB) U1.38(PGNDB) U1.41(PGNDA) U1.42(PGNDA) U1.48(PGND) U1.49(PGND) U1.54(FBGND) U1.57(EP)
VCC18-LPDDR3: R6.2
VCC18-RTC: C16.2 R4.1 R5.1 R6.1 R56.1
VDD-CPU: C10.2 C15.2 L9.1 L10.1
VDD-GPU: C21.2 L1.1
AP-NMI: R56.2 U1.16(IRQ)
AP-RESET: C11.2 U1.15(PWROK)
LXA: L10.2 U1.43(LXA) U1.44(LXA)
LXB: L9.2 U1.35(LXB) U1.36(LXB)
LXC: L1.2 U1.50(LXC) U1.51(LXC)
LXD: L8.2 U1.7(LXD)
LXE: L7.2 U1.12(LXE)
PMU-SCK: R2.2 U1.23(SCK)
PMU-SDA: R3.2 U1.24(SDA)
POWER: U1.27(EN)
VDD-CPUFB: U1.39(DCDCB) U1.40(DCDCA)
VDD-GPUFB: U1.47(DCDCC)
NetC25_1: C25.1 U1.29(VREF)
NetR4_2: R4.2 U1.25(VINT)
NetR5_2: R5.2 U1.26(PHSET)

Not connected (* = marked no-connect by the designer): U1 5(BLDO4)* 14(GPO)* 21(SWIN)* 22(SWOUT)* 55(MODESET)* 56(DCBSET)*

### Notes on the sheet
- BLDO
- CLDO
- DCDCC
- 连接标识处
- DCDC
- AXP805
- (near C21) 0.9V
- (near C27) DCDCD
- ALDO
- 0.9V
- 1.8V
- 3.3V
- LDO
- (near C4) DCDCE
- (near C4) 1.2V
- DCDCB
- DCDCA

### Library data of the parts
C1-C3 C16 = CL10A475KO8NNNC: 容值:4.7uF;精度:±10%;额定电压:16V;温度系数:X5R;; Manufacturer: SAMSUNG(三星); AddInBom: yes; ModelId: ac125912035d415993ca9572d50418b1¦0819f05c4eef4c71ace90d822a990e87; ModelName: C0603_L1.6-W0.8-H0.8; ModelTransform: 62.992,31.496,0,0,0,0,0,0,0; Tolerance: ±10%; Voltage Rating: 16V; Temperature Coefficient: X5R
C4 C5 C7-C10 C12-C15 C17-C20 C27-C29 = FCC0603X106K100CT: 容值:10uF;精度:±10%;额定电压:10V;温度系数:X5R;; Manufacturer: FOJAN(富捷); AddInBom: yes; ModelId: ac125912035d415993ca9572d50418b1¦0819f05c4eef4c71ace90d822a990e87; ModelName: C0603_L1.6-W0.8-H0.8; ModelTransform: 62.992,31.496,0,0,0,0,0,0,0; Tolerance: ±10%; Voltage Rating: 10V; Temperature Coefficient: X5R
C6 C21 = FCC0603X106K100CT: as C93 on sheet Lpddr3
C11 = CC0603KRX7R9BB102: 容值:1nF;精度:±10%;额定电压:50V;材质(温度系数):X7R;; Manufacturer: YAGEO(国巨); AddInBom: yes; ModelId: ac125912035d415993ca9572d50418b1¦0819f05c4eef4c71ace90d822a990e87; ModelName: C0603_L1.6-W0.8-H0.8; ModelTransform: 62.992,31.496,0,0,0,0,0,0,0; Tolerance: ±10%; Voltage Rated: 50V; Temperature Coefficient: X7R
C25 = CL10A105KO8NNNC: 容值:1uF;精度:±10%;额定电压:16V;温度系数:X5R;; Manufacturer: SAMSUNG(三星); AddInBom: yes; ModelId: ac125912035d415993ca9572d50418b1¦0819f05c4eef4c71ace90d822a990e87; ModelName: C0603_L1.6-W0.8-H0.8; ModelTransform: 62.992,31.496,0,0,0,0,0,0,0; Tolerance: ±10%; Voltage Rating: 16V; Temperature Coefficient: X5R
L1 L7-L10 = FXL0420-1R5-M: 电感值:1.5uH;精度:±20%;额定电流:5A;饱和电流(Isat):6A;类型:一体成型电感;; Manufacturer: cjiang(长江微电); AddInBom: yes; ModelId: e9b3d3f4fa134185b54d517730715f16¦0819f05c4eef4c71ace90d822a990e87; ModelName: IND-SMD_L4.2-W4.4-H2.0; ModelTransform: 173.228,165.354,0,0,0,0,0,0,0; Tolerance: ±20%; Rated Current: 5A; Saturation Current (Isat): 6A; DC Resistance (DCR): 46mΩ; Type: 一体成型电感
R2 R3 = RC0805FR-072KL: 电阻类型:厚膜电阻;阻值:2kΩ;精度:±1%;功率:125mW;最大工作电压:150V;温度系数:±100ppm/℃;; Manufacturer: YAGEO(国巨); AddInBom: yes; ModelId: 37a81e68749a4138bd2dfa6897b24b85¦0819f05c4eef4c71ace90d822a990e87; ModelName: R0805_L2.0-W1.3-H0.6; ModelTransform: 78.74,51.181,0,0,0,0,0,-0.0005,0; Tolerance: ±1%; Power(Watts): 125mW; Overload Voltage (Max): 150V
R4-R6 = RE0805FAR000: 电阻类型:合金电阻;阻值:0Ω;精度:±1%;功率:500mW;温度系数:±50ppm/℃;安装方式:贴片;; Manufacturer: JIERR(捷而瑞); AddInBom: yes; ModelId: 37a81e68749a4138bd2dfa6897b24b85¦0819f05c4eef4c71ace90d822a990e87; ModelName: R0805_L2.0-W1.3-H0.6; ModelTransform: 78.74,51.181,0,0,0,0,0,-0.0005,0; Tolerance: ±1%; Power(Watts): 500mW
R56 = FRC0805F1002TS: as R1 on sheet H6_SOC_1
U1 = AXP805: AddInBom: yes; ModelId: 7c0a5c04f6a841b49a7507ed380dda4c¦0819f05c4eef4c71ace90d822a990e87; ModelTransform: 276.377,276.377,0,0,0,0,0,0,0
